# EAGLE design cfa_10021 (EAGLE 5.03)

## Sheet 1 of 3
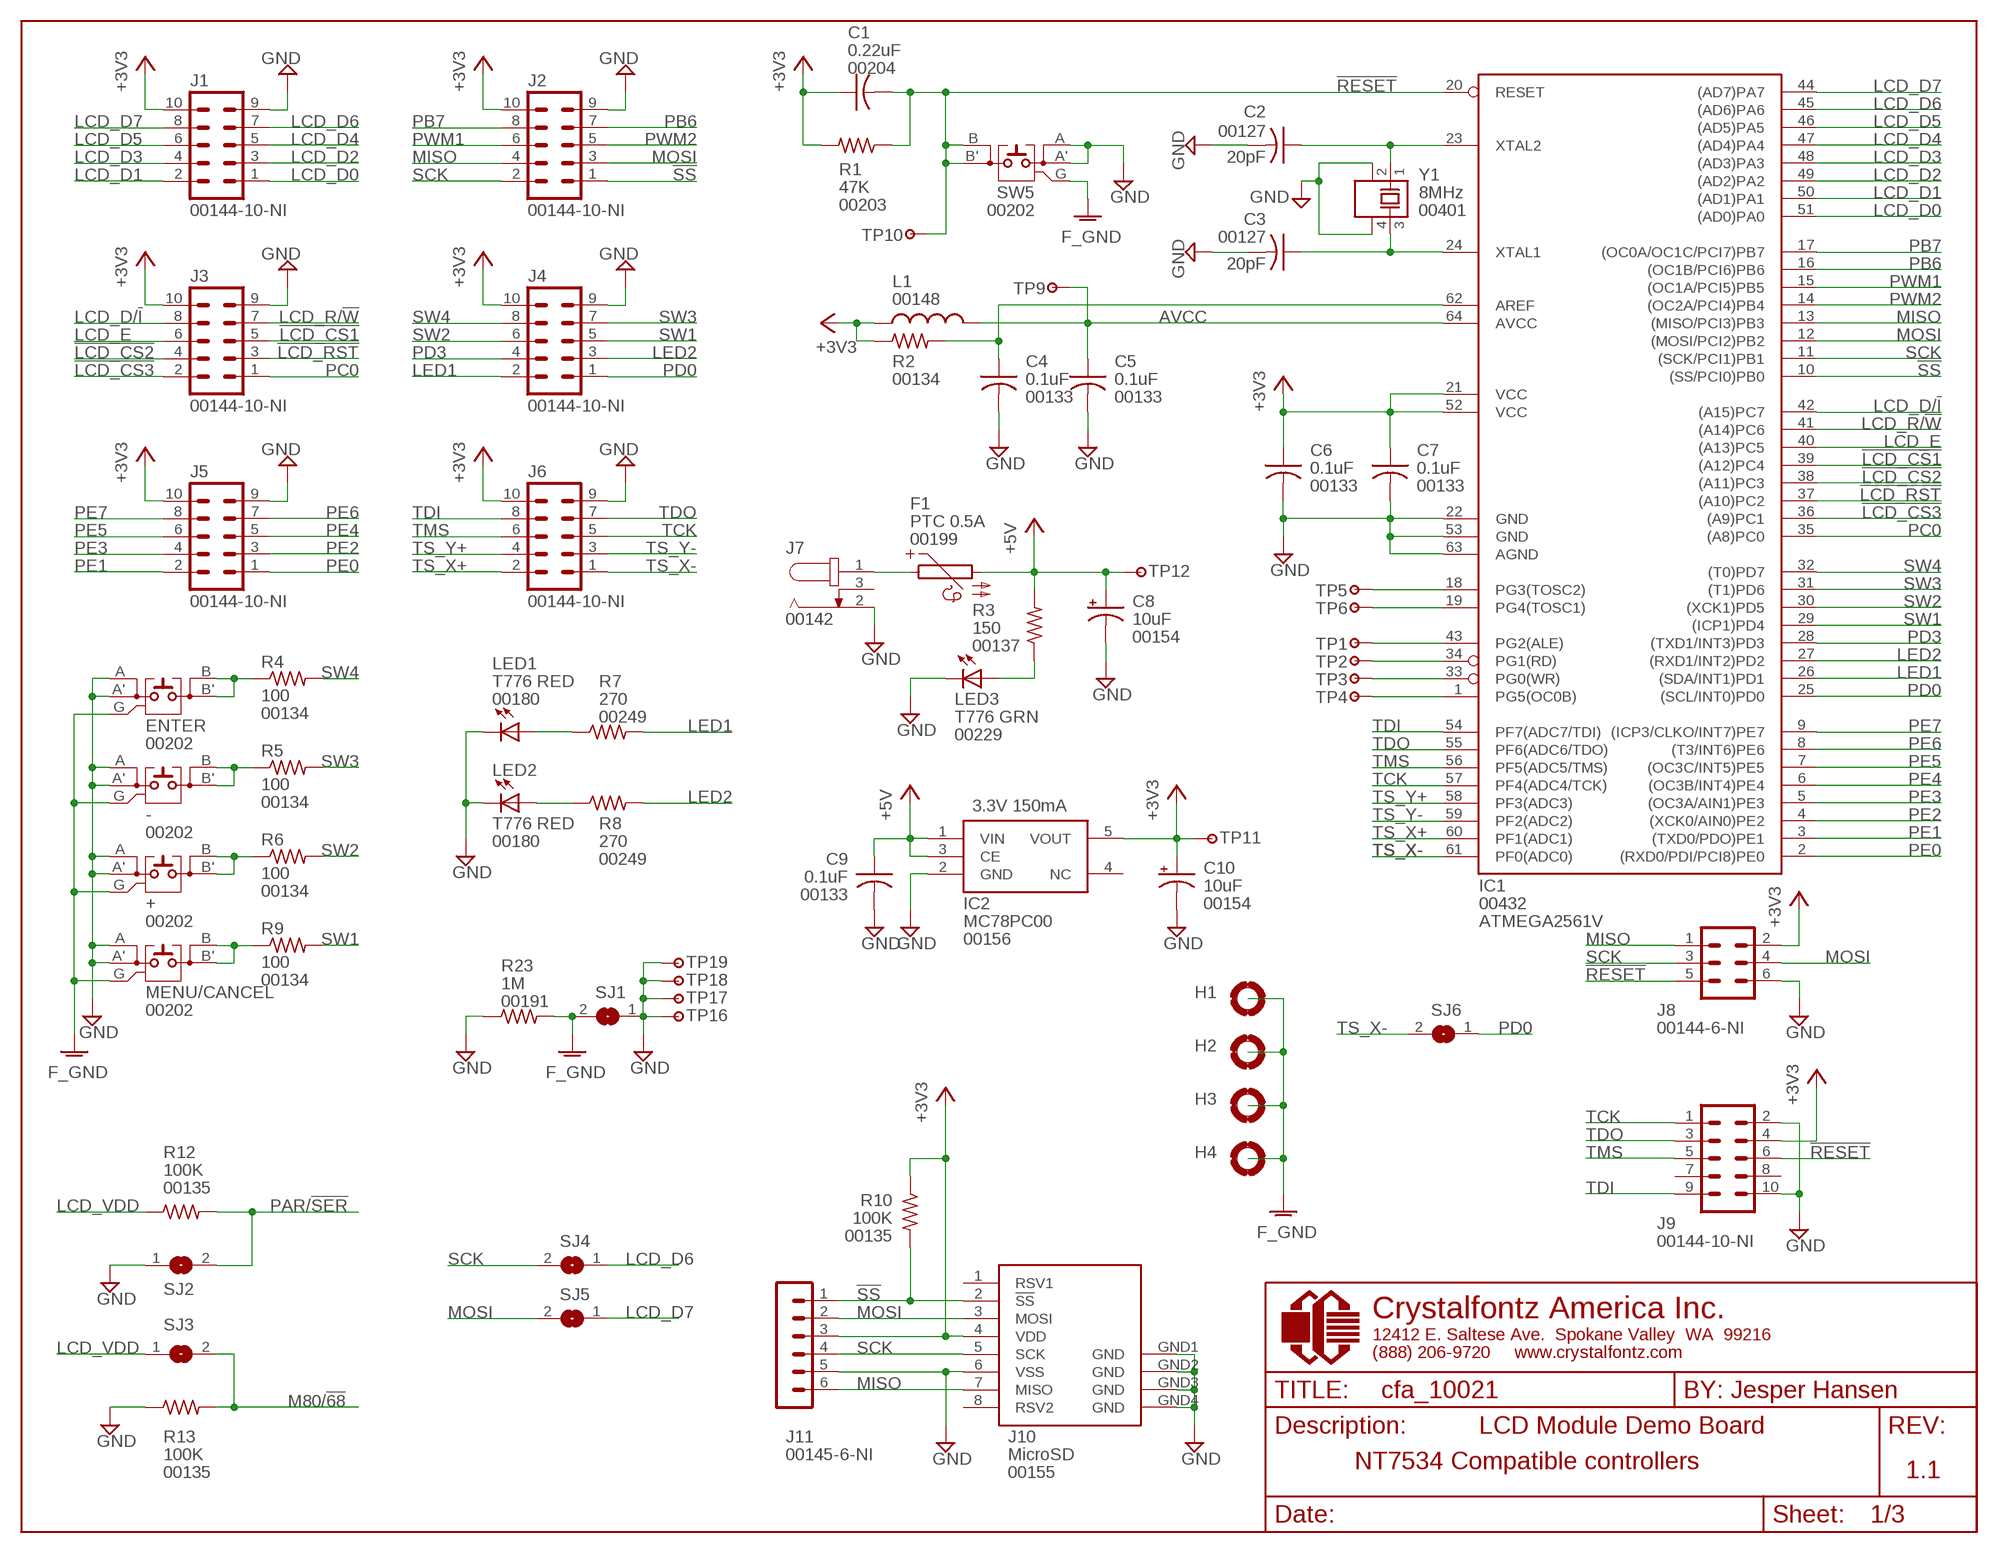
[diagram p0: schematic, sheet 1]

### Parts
+  00202  [EVQPB]
-  00202  [EVQPB]
C1  00204  [CAPC1608X90N]
C2  00127  [CAPC1608X87N]
C3  00127  [CAPC1608X87N]
C4  00133  [CAPC1608X87N]
C5  00133  [CAPC1608X87N]
C6  00133  [CAPC1608X87N]
C7  00133  [CAPC1608X87N]
C8  00154  [CAPMP6032X250N]
C9  00133  [CAPC1608X87N]
C10  00154  [CAPMP6032X250N]
ENTER  00202  [EVQPB]
F1  00199  [RESC3216X85N]
H1  MOUNT-PAD-ROUND3.2  [3,2-PAD]
H2  MOUNT-PAD-ROUND3.2  [3,2-PAD]
H3  MOUNT-PAD-ROUND3.2  [3,2-PAD]
H4  MOUNT-PAD-ROUND3.2  [3,2-PAD]
IC1  00432  [TQFP64-AEB]
IC2  00156  [SOT23-5L]
J1  00144-10-NI  [MA05-2]
J2  00144-10-NI  [MA05-2]
J3  00144-10-NI  [MA05-2]
J4  00144-10-NI  [MA05-2]
J5  00144-10-NI  [MA05-2]
J6  00144-10-NI  [MA05-2]
J7  00142  [PJ-102AH]
J8  00144-6-NI  [MA03-2]
J9  00144-10-NI  [MA05-2]
J10  00155  [3M_MICROSD]
J11  00145-6-NI  [MA06-1]
L1  00148  [R0805]
LED1  00180  [T776_LED_BOTTOM]
LED2  00180  [T776_LED_BOTTOM]
LED3  00229  [T776_LED_BOTTOM]
MENU/CANCEL  00202  [EVQPB]
R1  00203  [RESC1608X50N]
R2  00134  [RESC1608X38N]
R3  00137  [R0603]
R4  00134  [RESC1608X38N]
R5  00134  [RESC1608X38N]
R6  00134  [RESC1608X38N]
R7  00249  00137  [R0603]
R8  00249  00137  [R0603]
R9  00134  [RESC1608X38N]
R10  00135  [RESC1608X38N]
R12  00135  [RESC1608X38N]
R13  00135  [RESC1608X38N]
R23  00191  [RESC1608X55N]
SJ1  SJ  [SJ]
SJ2  SJ  [SJ]
SJ3  SJ  [SJ]
SJ4  SJ  [SJ]
SJ5  SJ  [SJ]
SJ6  SJ  [SJ]
SW5  00202  [EVQPB]
TP1  TP-VIA-3.2MM  [VIA-3.2MM-HOLE]
TP2  TP-VIA-3.2MM  [VIA-3.2MM-HOLE]
TP3  TP-VIA-3.2MM  [VIA-3.2MM-HOLE]
TP4  TP-VIA-3.2MM  [VIA-3.2MM-HOLE]
TP5  TP-VIA-3.2MM  [VIA-3.2MM-HOLE]
TP6  TP-VIA-3.2MM  [VIA-3.2MM-HOLE]
TP9  TP-VIA-1.0MM  [VIA-1MM-HOLE]
TP10  TP-VIA-1.0MM  [VIA-1MM-HOLE]
TP11  TP-VIA-1.0MM  [VIA-1MM-HOLE]
TP12  TP-VIA-1.0MM  [VIA-1MM-HOLE]
TP16  TP-VIA-1.0MM  [VIA-1MM-HOLE]
TP17  TP-VIA-1.0MM  [VIA-1MM-HOLE]
TP18  TP-VIA-1.0MM  [VIA-1MM-HOLE]
TP19  TP-VIA-1.0MM  [VIA-1MM-HOLE]
Y1  00401  [ABM3B]

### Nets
!LCD_CS1: IC1.39((A12)PC4) J3.5 ; also sheet 2
!LCD_CS2: IC1.38((A11)PC3) J3.4
!LCD_CS3: IC1.36((A9)PC1) J3.2
!LCD_RST: IC1.37((A10)PC2) J3.3 ; also sheet 2
!RESET: C1.2 IC1.20(RESET) J8.5 J9.6 R1.1 SW5.B SW5.B' TP10.1
!SS: IC1.10((SS/PCI0)PB0) J2.1 J10.2(!SS) J11.1 R10.2
+3V3: C1.1 C6.1 C7.1 C10.1(+) IC1.21(VCC) IC1.52(VCC) IC2.5(VOUT) J1.10 J2.10 J3.10 J4.10 J5.10 J6.10 J8.2 J9.4 J10.4(VDD) J11.3 L1.1 R1.2 R2.1 R10.1 TP11.1 ; also sheet 2
+5V: C8.1(+) C9.1 F1.2 IC2.1(VIN) IC2.3(CE) R3.2 TP12.1 ; also sheet 2
AVCC: C5.1 IC1.64(AVCC) L1.2 TP9.1
FOO: +.A +.A' -.A -.A' C2.2 C3.2 C4.2 C5.2 C6.2 C7.2 C8.2(-) C9.2 C10.2(-) ENTER.A ENTER.A' IC1.22(GND) IC1.53(GND) IC1.63(AGND) IC2.2(GND) J1.9 J2.9 J3.9 J4.9 J5.9 J6.9 J7.2 J8.6 J9.2 J9.10 J10.6(VSS) J10.GND1(GND) J10.GND2(GND) J10.GND3(GND) J10.GND4(GND) J11.5 LED1.K(C) LED2.K(C) LED3.K(C) MENU/CANCEL.A MENU/CANCEL.A' R13.1 R23.1 SJ1.1 SJ2.1 SW5.A SW5.A' TP16.1 TP17.1 TP18.1 TP19.1 Y1.2(GND) Y1.4(GND) ; supply symbol labelled GND ; also sheet 2
GNDA: +.G -.G ENTER.G H1.B3,2(MOUNT) H2.B3,2(MOUNT) H3.B3,2(MOUNT) H4.B3,2(MOUNT) MENU/CANCEL.G R23.2 SJ1.2 SW5.G ; supply symbol labelled F_GND
LCD_D0: IC1.51((AD0)PA0) J1.1 ; also sheet 2
LCD_D1: IC1.50((AD1)PA1) J1.2 ; also sheet 2
LCD_D2: IC1.49((AD2)PA2) J1.3 ; also sheet 2
LCD_D3: IC1.48((AD3)PA3) J1.4 ; also sheet 2
LCD_D4: IC1.47((AD4)PA4) J1.5 ; also sheet 2
LCD_D5: IC1.46((AD5)PA5) J1.6 ; also sheet 2
LCD_D6: IC1.45((AD6)PA6) J1.7 SJ4.1 ; also sheet 2
LCD_D7: IC1.44((AD7)PA7) J1.8 SJ5.1 ; also sheet 2
LCD_D/!I: IC1.42((A15)PC7) J3.8 ; also sheet 2
LCD_E: IC1.40((A13)PC5) J3.6 ; also sheet 2
LCD_R/!W: IC1.41((A14)PC6) J3.7 ; also sheet 2
LCD_VDD: R12.1 SJ3.1 ; also sheet 2
LED1: IC1.26((SDA/INT1)PD1) J4.2 R7.2
LED2: IC1.27((RXD1/INT2)PD2) J4.3 R8.2
M80/!68: R13.2 SJ3.2 ; also sheet 2
MISO: IC1.13((MISO/PCI3)PB3) J2.4 J8.1 J10.7(MISO) J11.6
MOSI: IC1.12((MOSI/PCI2)PB2) J2.3 J8.4 J10.3(MOSI) J11.2 SJ5.2
N$1: C2.1 IC1.23(XTAL2) Y1.1
N$2: ENTER.B ENTER.B' R4.1
N$3: C3.1 IC1.24(XTAL1) Y1.3
N$4: -.B -.B' R5.1
N$5: IC1.19(PG4(TOSC1)) TP6.1
N$6: +.B +.B' R6.1
N$7: LED1.A R7.1
N$8: MENU/CANCEL.B MENU/CANCEL.B' R9.1
N$9: C4.1 IC1.62(AREF) R2.2
N$10: LED2.A R8.1
N$11: IC1.43(PG2(ALE)) TP1.1
N$13: IC1.34(PG1(RD)) TP2.1
N$14: F1.1 J7.1
N$15: IC1.33(PG0(WR)) TP3.1
N$17: LED3.A R3.1
N$18: IC1.18(PG3(TOSC2)) TP5.1
N$19: IC1.1(PG5(OC0B)) TP4.1
PAR/!SER: R12.2 SJ2.2 ; also sheet 2
PB6: IC1.16((OC1B/PCI6)PB6) J2.7
PB7: IC1.17((OC0A/OC1C/PCI7)PB7) J2.8
PC0: IC1.35((A8)PC0) J3.1
PD0: IC1.25((SCL/INT0)PD0) J4.1 SJ6.1
PD3: IC1.28((TXD1/INT3)PD3) J4.4
PE0: IC1.2((RXD0/PDI/PCI8)PE0) J5.1
PE1: IC1.3((TXD0/PDO)PE1) J5.2
PE2: IC1.4((XCK0/AIN0)PE2) J5.3
PE3: IC1.5((OC3A/AIN1)PE3) J5.4
PE4: IC1.6((OC3B/INT4)PE4) J5.5
PE5: IC1.7((OC3C/INT5)PE5) J5.6
PE6: IC1.8((T3/INT6)PE6) J5.7
PE7: IC1.9((ICP3/CLKO/INT7)PE7) J5.8
PWM1: IC1.15((OC1A/PCI5)PB5) J2.6 ; also sheet 2
PWM2: IC1.14((OC2A/PCI4)PB4) J2.5 ; also sheet 2
SCK: IC1.11((SCK/PCI1)PB1) J2.2 J8.3 J10.5(SCK) J11.4 SJ4.2
SW1: IC1.29((ICP1)PD4) J4.5 R9.2
SW2: IC1.30((XCK1)PD5) J4.6 R6.2
SW3: IC1.31((T1)PD6) J4.7 R5.2
SW4: IC1.32((T0)PD7) J4.8 R4.2
TCK: IC1.57(PF4(ADC4/TCK)) J6.5 J9.1
TDI: IC1.54(PF7(ADC7/TDI)) J6.8 J9.9
TDO: IC1.55(PF6(ADC6/TDO)) J6.7 J9.3
TMS: IC1.56(PF5(ADC5/TMS)) J6.6 J9.5
TS_X+: IC1.60(PF1(ADC1)) J6.2 ; also sheet 2
TS_X-: IC1.61(PF0(ADC0)) J6.1 SJ6.2 ; also sheet 2
TS_Y+: IC1.58(PF3(ADC3)) J6.4 ; also sheet 2
TS_Y-: IC1.59(PF2(ADC2)) J6.3 ; also sheet 2
Unconnected: IC2.4(NC) J7.3 J9.7 J9.8 J10.1(RSV1) J10.8(RSV2)

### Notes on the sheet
- 0.22uF
- 20pF
- 47K
- 8MHz
- 20pF
- 0.1uF | 0.1uF
- 0.1uF | 0.1uF
- PTC 0.5A
- 10uF
- 150
- T776 RED
- 100 | 270
- T776 GRN
- 100
- 3.3V 150mA
- T776 RED
- 270
- 100 | 0.1uF
- 10uF
- MC78PC00 | ATMEGA2561V
- 100
- 1M
- 100K
- 100K
- LCD Module Demo Board
- 100K | MicroSD
- NT7534 Compatible controllers
- 1.1

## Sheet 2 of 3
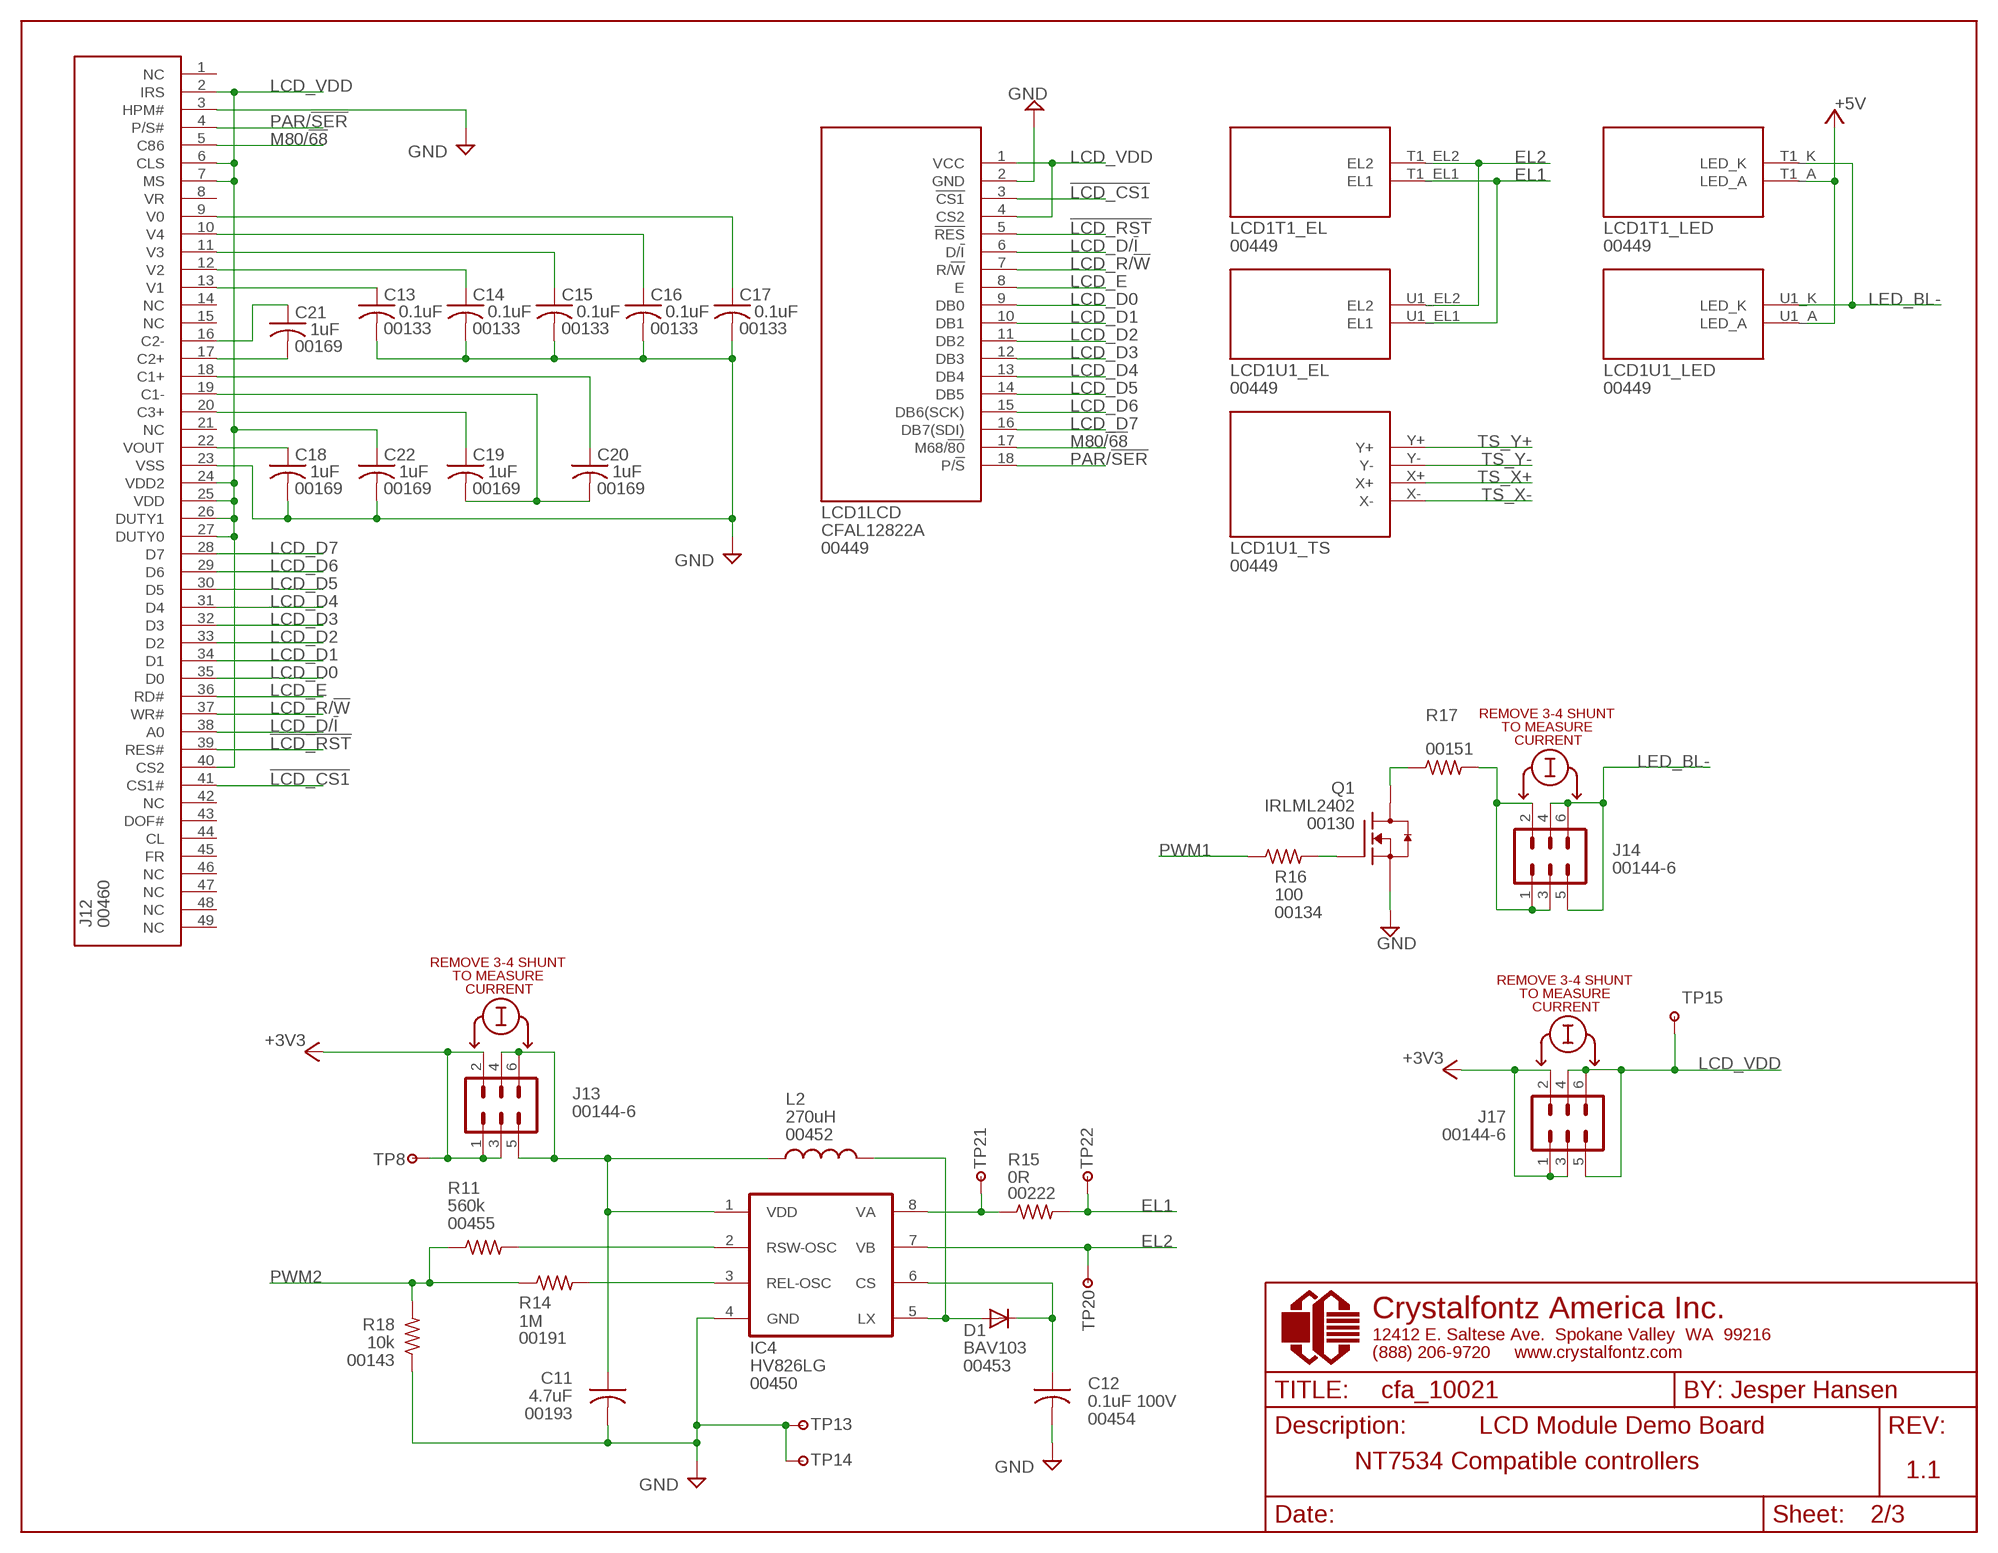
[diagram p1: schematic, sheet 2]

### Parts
C11  00193  [CAPC2012X51N]
C12  00454  [C0805]
C13  00133  [CAPC1608X87N]
C14  00133  [CAPC1608X87N]
C15  00133  [CAPC1608X87N]
C16  00133  [CAPC1608X87N]
C17  00133  [CAPC1608X87N]
C18  00169  [CAPC2012X125N]
C19  00169  [CAPC2012X125N]
C20  00169  [CAPC2012X125N]
C21  00169  [CAPC2012X125N]
C22  00169  [CAPC2012X125N]
D1  00453  [SOD80C]
IC4  00450  [SO08]
J12  00460  [CFAX12864_TAB]
J13  00144-6  [MA03-2]
J14  00144-6  [MA03-2]
J17  00144-6  [MA03-2]
L2  00452  [IND-1210]
LCD1  00449  [CFAX12864_ALL]
Q1  00130  [SOT23]
R11  00455  [RESC1608X55N]
R14  00191  [RESC1608X55N]
R15  00222  [RESC1608X38N]
R16  00134  [RESC1608X38N]
R17  00151  [R2010]
R18  00143  [RESC1608X38N]
TP8  TP-VIA-1.0MM  [VIA-1MM-HOLE]
TP13  TP-VIA-1.0MM  [VIA-1MM-HOLE]
TP14  TP-VIA-1.0MM  [VIA-1MM-HOLE]
TP15  TP-VIA-1.0MM  [VIA-1MM-HOLE]
TP20  TP-VIA-1.0MM  [VIA-1MM-HOLE]
TP21  TP-VIA-1.0MM  [VIA-1MM-HOLE]
TP22  TP-VIA-1.0MM  [VIA-1MM-HOLE]

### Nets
!LCD_CS1: J12.41(CS1#) LCD1.3(LCD:!CS1) ; also sheet 1
!LCD_RST: J12.39(RES#) LCD1.5(LCD:!RES) ; also sheet 1
+3V3: J13.1 J13.2 J13.3 J17.1 J17.2 J17.3 TP8.1 ; also sheet 1
+5V: LCD1.T1_A(T1_LED:LED_A) LCD1.U1_A(U1_LED:LED_A) ; also sheet 1
EL1: LCD1.T1_EL1(T1_EL:EL1) LCD1.U1_EL1(U1_EL:EL1) R15.2 TP22.1
EL2: IC4.7(VB) LCD1.T1_EL2(T1_EL:EL2) LCD1.U1_EL2(U1_EL:EL2) TP20.1
FOO: C11.2 C12.2 C13.2 C14.2 C15.2 C16.2 C17.2 C18.2 C22.2 IC4.4(GND) J12.3(HPM#) J12.23(VSS) LCD1.2(LCD:GND) Q1.2(S) R18.1 TP13.1 TP14.1 ; supply symbol labelled GND ; also sheet 1
LCD_D0: J12.35(D0) LCD1.9(LCD:DB0) ; also sheet 1
LCD_D1: J12.34(D1) LCD1.10(LCD:DB1) ; also sheet 1
LCD_D2: J12.33(D2) LCD1.11(LCD:DB2) ; also sheet 1
LCD_D3: J12.32(D3) LCD1.12(LCD:DB3) ; also sheet 1
LCD_D4: J12.31(D4) LCD1.13(LCD:DB4) ; also sheet 1
LCD_D5: J12.30(D5) LCD1.14(LCD:DB5) ; also sheet 1
LCD_D6: J12.29(D6) LCD1.15(LCD:DB6(SCK)) ; also sheet 1
LCD_D7: J12.28(D7) LCD1.16(LCD:DB7(SDI)) ; also sheet 1
LCD_D/!I: J12.38(A0) LCD1.6(LCD:D/!I) ; also sheet 1
LCD_E: J12.36(RD#) LCD1.8(LCD:E) ; also sheet 1
LCD_R/!W: J12.37(WR#) LCD1.7(LCD:R/!W) ; also sheet 1
LCD_VDD: C22.1 J12.2(IRS) J12.6(CLS) J12.7(MS) J12.24(VDD2) J12.25(VDD) J12.26(DUTY1) J12.27(DUTY0) J12.40(CS2) J17.4 J17.5 J17.6 LCD1.1(LCD:VCC) LCD1.4(LCD:CS2) TP15.1 ; also sheet 1
LED_BL-: J14.4 J14.5 J14.6 LCD1.T1_K(T1_LED:LED_K) LCD1.U1_K(U1_LED:LED_K)
M80/!68: J12.5(C86) LCD1.17(LCD:M68/!80) ; also sheet 1
N$12: C12.1 D1.C IC4.6(CS)
N$16: IC4.8(VA) R15.1 TP21.1
N$20: IC4.2(RSW-OSC) R11.2
N$21: IC4.3(REL-OSC) R14.2
N$22: C11.1 IC4.1(VDD) J13.4 J13.5 J13.6 L2.1
N$25: J14.1 J14.2 J14.3 R17.2
N$28: C18.1 J12.22(VOUT)
N$29: C19.2 C20.2 J12.19(C1-)
N$30: Q1.3(D) R17.1
N$31: Q1.1(G) R16.2
N$32: D1.A IC4.5(LX) L2.2
N$33: C19.1 J12.20(C3+)
N$34: C20.1 J12.18(C1+)
N$35: C21.2 J12.17(C2+)
N$36: C21.1 J12.16(C2-)
N$37: C13.1 J12.13(V1)
N$38: C14.1 J12.12(V2)
N$39: C15.1 J12.11(V3)
N$40: C16.1 J12.10(V4)
N$41: C17.1 J12.9(V0)
PAR/!SER: J12.4(P/S#) LCD1.18(LCD:P/!S) ; also sheet 1
PWM1: R16.1 ; also sheet 1
PWM2: R11.1 R14.1 R18.2 ; also sheet 1
TS_X+: LCD1.X+(U1_TS:X+) ; also sheet 1
TS_X-: LCD1.X-(U1_TS:X-) ; also sheet 1
TS_Y+: LCD1.Y+(U1_TS:Y+) ; also sheet 1
TS_Y-: LCD1.Y-(U1_TS:Y-) ; also sheet 1
Unconnected: J12.1(NC) J12.8(VR) J12.14(NC) J12.15(NC) J12.21(NC) J12.42(NC) J12.43(DOF#) J12.44(CL) J12.45(FR) J12.46(NC) J12.47(NC) J12.48(NC) J12.49(NC)

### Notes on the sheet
- 0.1uF | 0.1uF | 0.1uF | 0.1uF | 0.1uF
- 1uF
- 1uF | 1uF | 1uF | 1uF
- CFAL12822A
- REMOVE 3-4 SHUNT
- TO MEASURE
- CURRENT
- IRLML2402
- 100
- REMOVE 3-4 SHUNT
- TO MEASURE
- REMOVE 3-4 SHUNT
- CURRENT
- TO MEASURE
- CURRENT
- 270uH
- 0R
- 560k
- 1M
- 10k
- BAV103
- HV826LG
- 4.7uF
- 0.1uF 100V
- LCD Module Demo Board
- NT7534 Compatible controllers
- 1.1

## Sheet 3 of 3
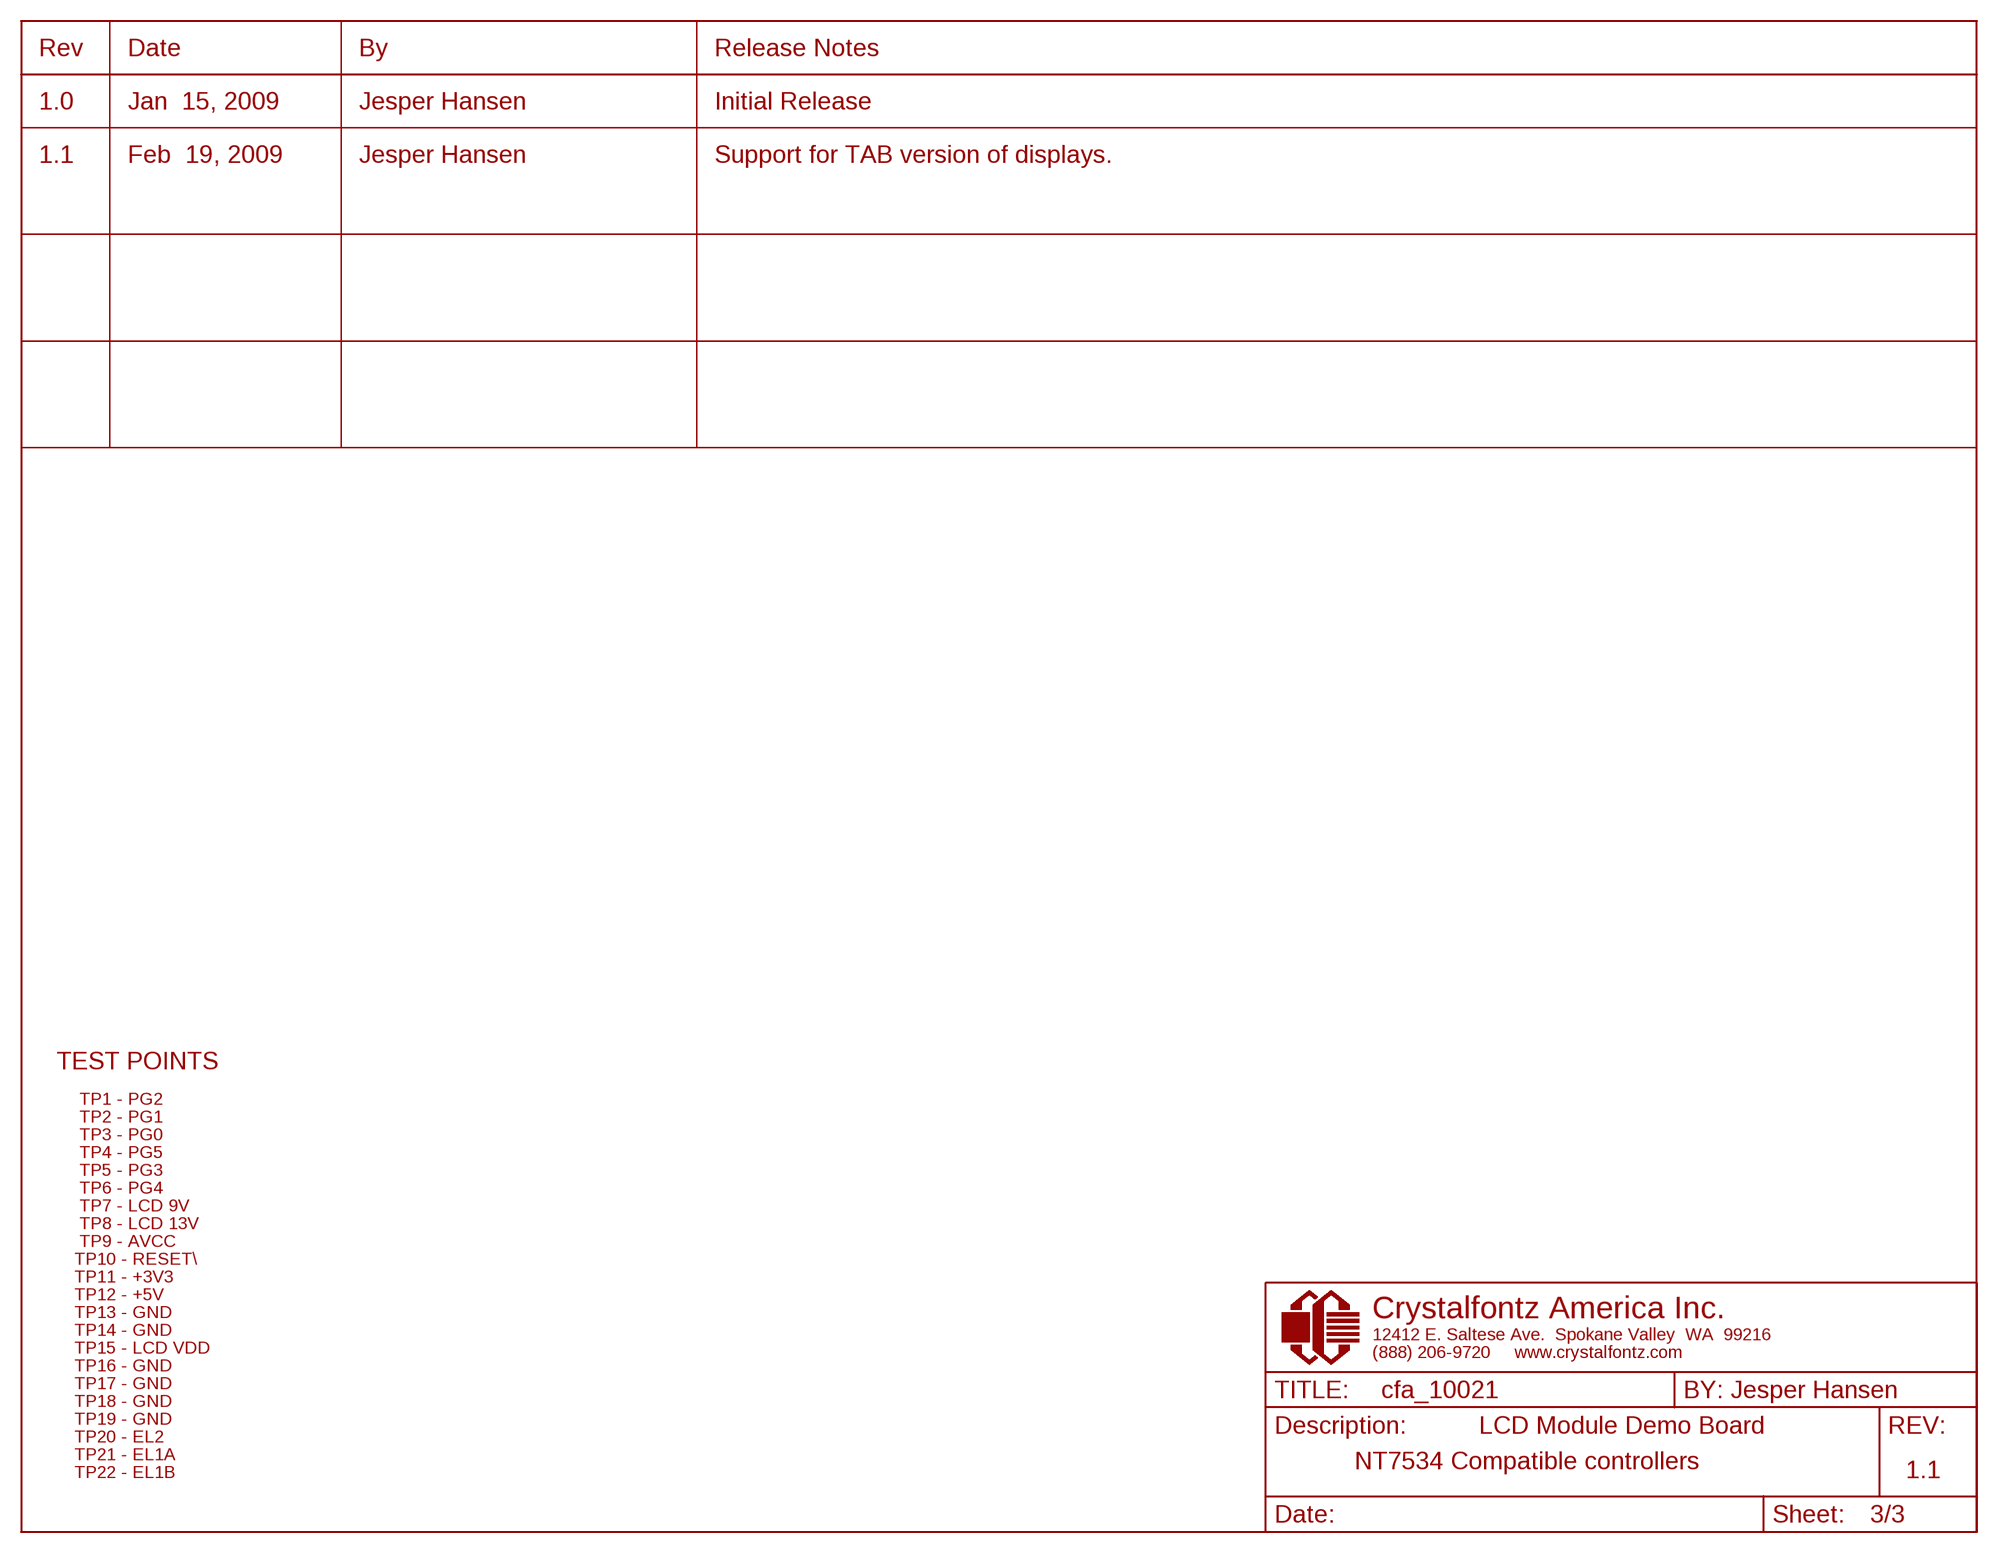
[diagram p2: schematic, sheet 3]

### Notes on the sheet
- Rev | Date | By | Release Notes
- 1.0 | Jan  15, 2009 | Jesper Hansen | Initial Release
- 1.1 | Feb  19, 2009 | Jesper Hansen | Support for TAB version of displays.
- TEST POINTS
- TP1 - PG2
- TP2 - PG1
- TP3 - PG0
- TP4 - PG5
- TP5 - PG3
- TP6 - PG4
- TP7 - LCD 9V
- TP8 - LCD 13V
- TP9 - AVCC
- TP10 - RESET\\
- TP11 - +3V3
- TP12 - +5V
- TP13 - GND
- TP14 - GND
- TP15 - LCD VDD
- TP16 - GND
- TP17 - GND
- TP18 - GND
- TP19 - GND
- LCD Module Demo Board
- TP20 - EL2
- TP21 - EL1A
- NT7534 Compatible controllers
- TP22 - EL1B | 1.1

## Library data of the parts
+ - ENTER MENU/CANCEL SW5 = proddev_lib:00202: SPST MOM W/GND, 6MM LIGHT TOUCH SW W/GND H=7 TH
C1 = proddev_lib:00204: 0.22uF 10V, CAP .22UF 10V CERAMIC X5R 0603
C2 C3 = proddev_lib:00127: 20pF, CAP CER 20PF 50V 5% C0G 0603
C4-C7 C9 C13-C17 = proddev_lib:00133: 0.1uF 16V, CAP .1UF 16V CERAMIC X7R 0603
C8 C10 = proddev_lib:00154: 10uF 10V, CAP TANT 10UF 10V 10% LOESR SMD
C11 = proddev_lib:00193: 4.7UF 10V, CAP CER 4.7UF 10V X7R 0805
C12 = proddev_lib2:00454: CAP CER .10UF 100V X7R 10% 0805
C18-C22 = proddev_lib:00169: 1.0UF 35V, CAP CER 1.0UF 35V X7R 0805
D1 = proddev_lib2:00453: DIODE SW 200V 250MA SOD80C
F1 = proddev_lib:00199: 500mA, PTC RESETTABLE .50A 13.2V 1206
H1-H4 = holes:MOUNT-PAD-ROUND: MOUNTING PAD, round
IC1 = proddev_lib2:00432: ATmega2561V-8AU, IC AVR MCU 256K 8MHZ LOW-VOLTAGE 64TQFP 256 Kbytes FLASH 8 Kbytes SRAM 4 Kbytes EEPROM DUAL USART 8-channel 10 bit ADC
IC2 = proddev_lib:00156: MC78PC33, IC REG LDO 150MA 3.3V LN SOT23-5
IC4 = proddev_lib2:00450: HV826 High Voltage EL Lamp Driver Features 1.8 to 3.5V operating supply voltage DC to AC conversion Output voltage regulation Adjustable output lamp frequency Adjustable converter frequency Enable/disable function Applications Pagers Portable Transceiver Cellular phones Remote control units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
J1-J6 J9 = proddev_lib:00144-10-NI: 2X5 HDR, CONN HDR BRKWAY .100 VERT
J7 = proddev_lib:00142: 2.1x5.5MM, CONN PWR JACK 2.1X5.5MM HIGH CUR
J8 = proddev_lib:00144-6-NI: 2X3 HDR, CONN HDR BRKWAY .100 VERT
J10 = proddev_lib:00155: MICROSD SOCKET, CONN EJECT MICROSD PUSH-PUSH SMD
J11 = proddev_lib:00145-6-NI: 1X6 HDR, CONN HDR BRKWAY .100 VERT
J12 = proddev_lib2:00460: TAB connector for CFAX displays
J13 J14 J17 = proddev_lib:00144-6: 2X3 HDR, CONN HDR BRKWAY .100 VERT
L1 = proddev_lib:00148: 10uH, FERRITE CHIP 1000 OHM 200MA 0805
L2 = proddev_lib2:00452: INDUCTOR 270UH 5% 40MA 1210
LCD1 = proddev_lib2:00449: Multidesign for all CFAX12864 variants
LED1 LED2 = proddev_lib:00180: LST776, LED SUP RED REV GULWNG 645NM SMD
LED3 = proddev_lib:00229: LED GRN, LED PURE GRN REV GLWNG 562NM SMD
Q1 = proddev_lib:00130: IRLML2402, MOSFET N-CH 20V 1.2A SOT-23
R1 = proddev_lib:00203: 47K 1/10W 5%, RES 47K OHM 1/10W 5% 0603 SMD
R2 R4-R6 R9 R16 = proddev_lib:00134: 100, RES 100 OHM 1/10W 5% 0603 SMD
R3 R7 R8 = proddev_lib:00137: 150, RES 150 OHM 1/10W 5% 0603 SMD
R10 R12 R13 = proddev_lib:00135: 100K, RES 100K OHM 1/10W 5% 0603 SMD
R11 = proddev_lib2:00455: RES 560K OHM 1/10W 1% 0603 SMD
R14 R23 = proddev_lib:00191: 1.0M 1/10W 1%, RES 1.00M OHM 1/10W 1% 0603 SMD
R15 = proddev_lib:00222: 0.0 OHM, RES 0.0 OHM 1/10W 5% 0603 SMD
R17 = proddev_lib:00151: R 1/2W 2010, BACKLIGHT RES 1/2W 2010 SMD
R18 = proddev_lib:00143: 10K, RES 10K OHM 1/10W 5% 0603 SMD
SJ1-SJ6 = proddev_lib:SJ: SMD solder JUMPER
TP1-TP6 = proddev_lib:TP-VIA-3.2MM: 3.2MM Hole Via TP
TP8-TP22 = proddev_lib:TP-VIA-1.0MM: TP 1MM HOLE
Y1 = proddev_lib2:00401: Crystal; ABM3B Ceramic SMD Crystal, 5x3.2mm

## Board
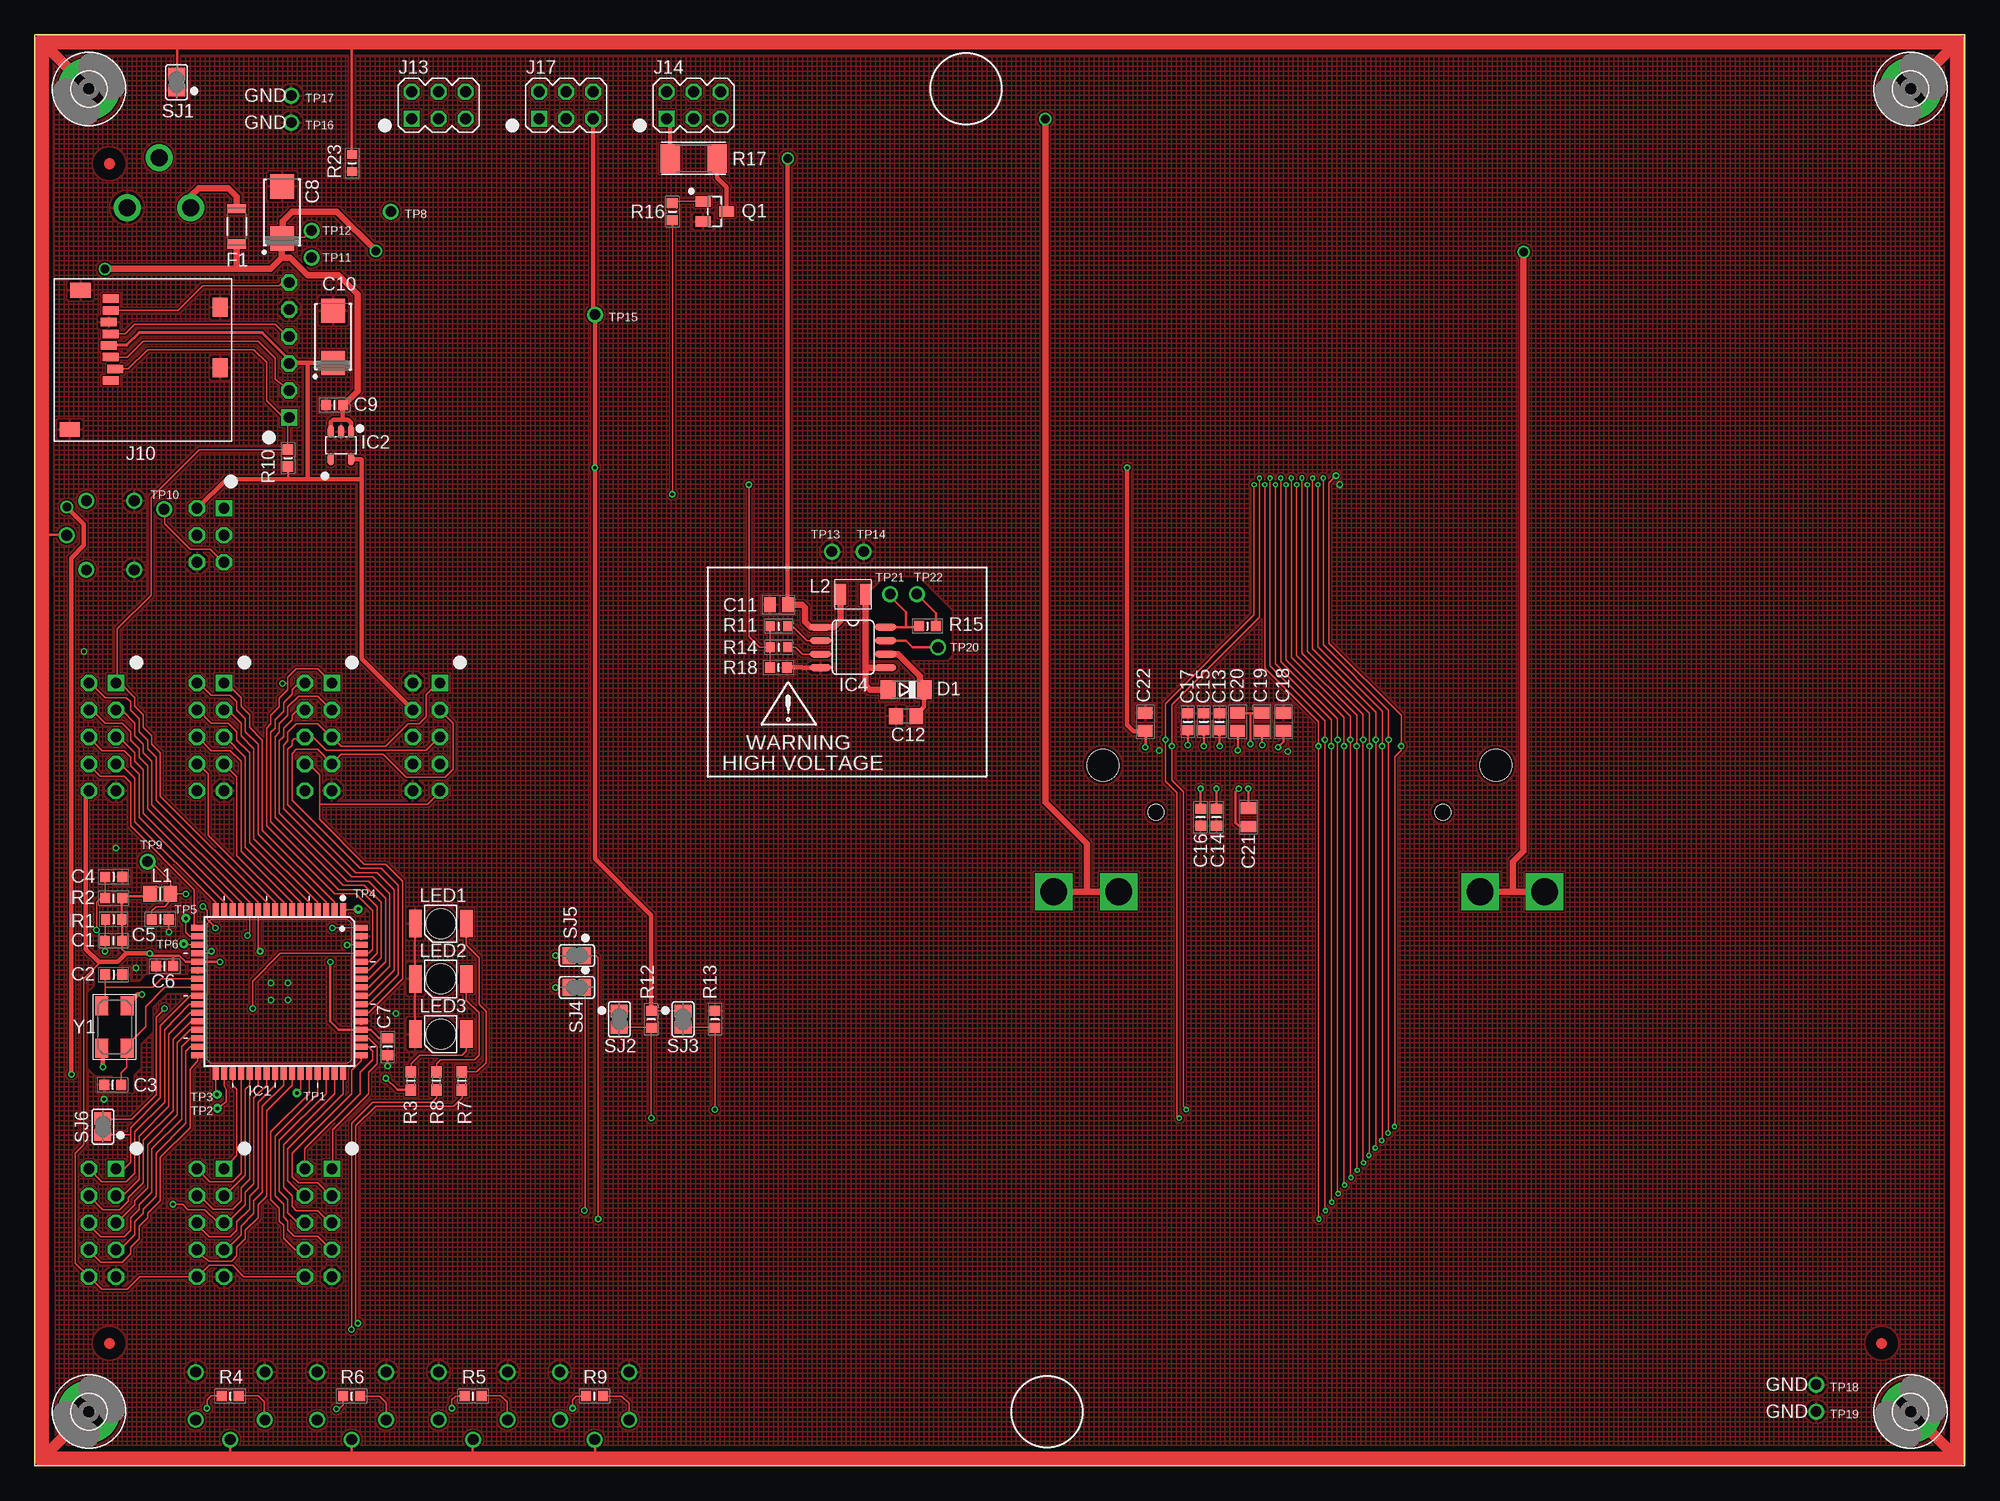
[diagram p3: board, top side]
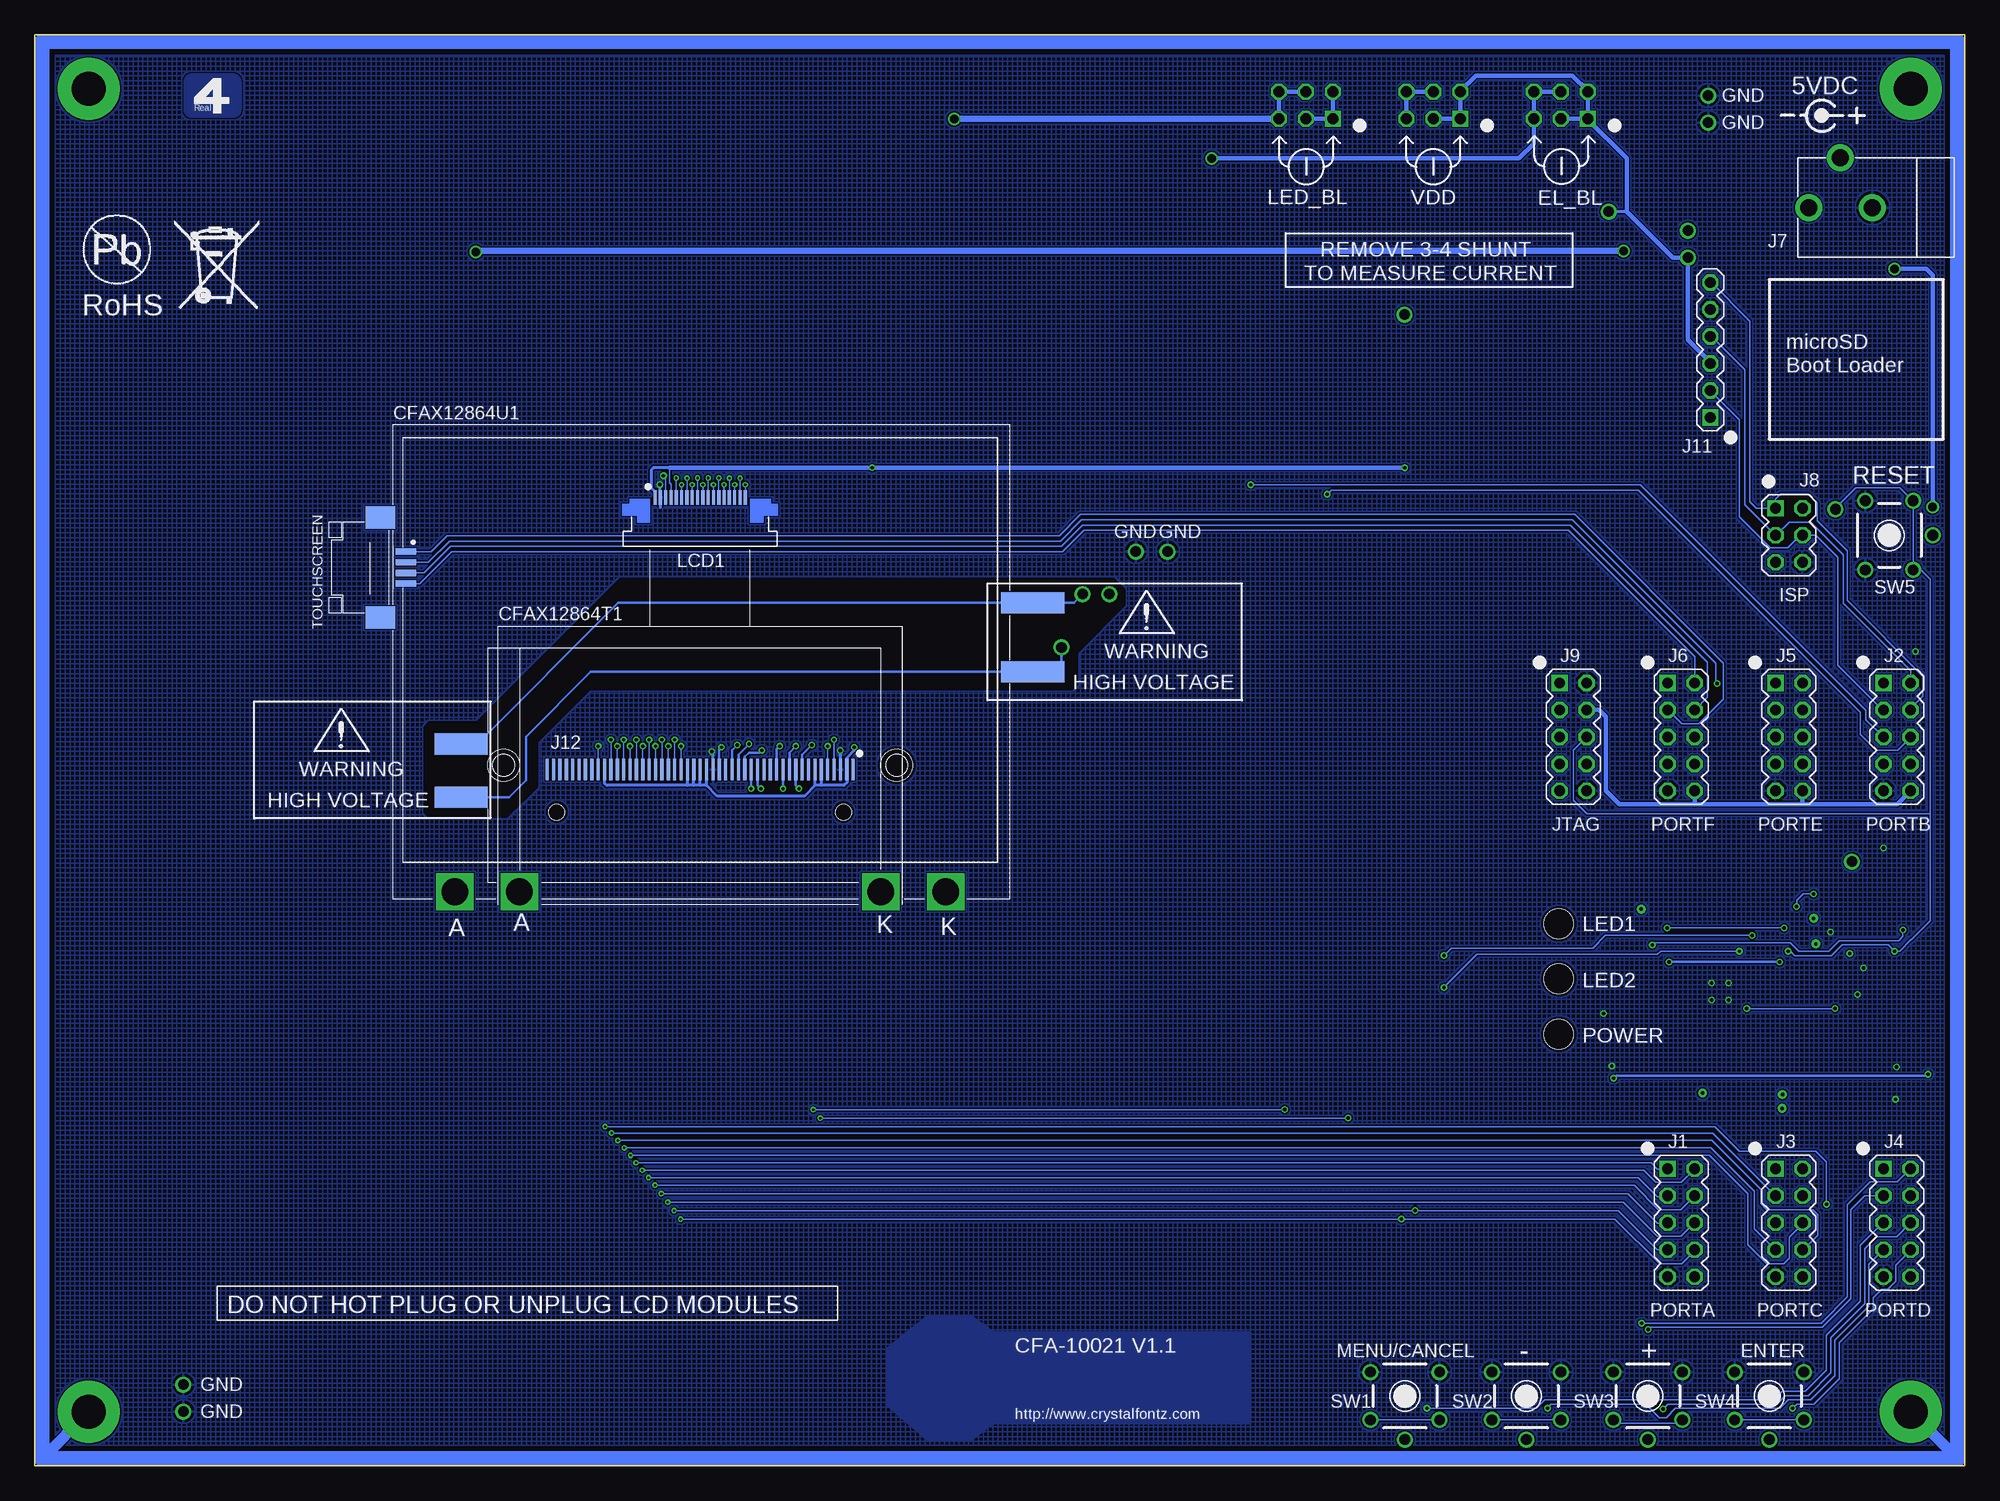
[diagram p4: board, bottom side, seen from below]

Size 181.61 x 134.62 mm. Coordinates in mm from the lower left corner, seen from the top.
Outline: 0,0 181.57,0 181.57,134.62 0,134.62
Outline: 0,0 181.61,0 181.61,134.62 0,134.62
Outline: 0,134.62 0,0
Copper layers (1*2+15*16): Top 0.0254mm / dielectric 0.2032mm / Route2 0.0254mm / dielectric 1.4986mm / Route15 0.0254mm / dielectric 0.2032mm / Bottom 0.0254mm
Design rules "cadint-2layer": minimum track width 5mil, minimum drill 0.31mm, track to track 5mil, track to pad 5mil, pad to pad 5mil, via to via 5mil, smd to smd 5mil, copper to edge 10mil, drill to drill 10mil, minimum pad ring 10mil, minimum via ring 6mil, stop-mask expansion 0mil, vias tented up to drill 0mil, thermal gap 10mil
tRestrict: area 5.5,10 to 8.5,13; area 5.5,121 to 8.5,124; area 172.3,10 to 175.3,13; area 5.1,35.2 to 16.2,46.7; area 78.4,75.9 to 86.2,83.5
bRestrict: area 79,61 to 145,83.5

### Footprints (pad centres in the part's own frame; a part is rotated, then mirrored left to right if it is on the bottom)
EVQPB = drill 1 round: A -2.25,3.25; A' -2.25,-3.25; B 2.25,3.25; B' 2.25,-3.25; G 4.1,0
CAPC1608X90N = smd 0.9 x 0.95: 1 -0.8,0; 2 0.8,0
CAPC1608X87N = smd 0.95 x 1: 1 -0.8,0; 2 0.8,0
CAPMP6032X250N = smd 2.3 x 2.25: 1 -2.45,0; 2 2.45,0
CAPC2012X51N = smd 1.1 x 1.4: 1 -0.85,0; 2 0.85,0
C0805 = smd 1.3 x 1.5: 1 -0.95,0; 2 0.95,0
CAPC2012X125N = smd 1.1 x 1.4: 1 -0.85,0; 2 0.85,0
SOD80C = smd 1.4 x 1.8: A 1.7,0; C -1.7,0
RESC3216X85N = smd 0.85 x 1.8: 1 -1.65,0; 2 1.65,0
3,2-PAD = drill 3.2 pad 5.842 round: B3,2 0,0
TQFP64-AEB = smd 1.194 x 0.559: 1 -7.7,6; 2 -7.7,5.2; 3 -7.7,4.4; 4 -7.7,3.6; 5 -7.7,2.8; 6 -7.7,2; 7 -7.7,1.2; 8 -7.7,0.4; 9 -7.7,-0.4; 10 -7.7,-1.2; 11 -7.7,-2; 12 -7.7,-2.8; 13 -7.7,-3.6; 14 -7.7,-4.4; 15 -7.7,-5.2; 16 -7.7,-6; 33 7.7,-6; 34 7.7,-5.2; 35 7.7,-4.4; 36 7.7,-3.6; 37 7.7,-2.8; 38 7.7,-2; 39 7.7,-1.2; 40 7.7,-0.4; 41 7.7,0.4; 42 7.7,1.2; 43 7.7,2; 44 7.7,2.8; 45 7.7,3.6; 46 7.7,4.4; 47 7.7,5.2; 48 7.7,6 | smd 0.559 x 1.194: 17 -6,-7.7; 18 -5.2,-7.7; 19 -4.4,-7.7; 20 -3.6,-7.7; 21 -2.8,-7.7; 22 -2,-7.7; 23 -1.2,-7.7; 24 -0.4,-7.7; 25 0.4,-7.7; 26 1.2,-7.7; 27 2,-7.7; 28 2.8,-7.7; 29 3.6,-7.7; 30 4.4,-7.7; 31 5.2,-7.7; 32 6,-7.7; 49 6,7.7; 50 5.2,7.7; 51 4.4,7.7; 52 3.6,7.7; 53 2.8,7.7; 54 2,7.7; 55 1.2,7.7; 56 0.4,7.7; 57 -0.4,7.7; 58 -1.2,7.7; 59 -2,7.7; 60 -2.8,7.7; 61 -3.6,7.7; 62 -4.4,7.7; 63 -5.2,7.7; 64 -6,7.7
SOT23-5L = smd 0.55 x 1.2: 1 -0.95,-1.3; 2 0,-1.3; 3 0.95,-1.3; 4 0.95,1.3; 5 -0.95,1.3
SO08 = smd 0.66 x 2.032: 1 -1.905,-3.073; 2 -0.635,-3.073; 3 0.635,-3.073; 4 1.905,-3.073; 5 1.905,3.073; 6 0.635,3.073; 7 -0.635,3.073; 8 -1.905,3.073
MA05-2 = drill 1.016 square: 1 -5.08,-1.27 | drill 1.016 octagon: 2 -5.08,1.27; 3 -2.54,-1.27; 4 -2.54,1.27; 5 0,-1.27; 6 0,1.27; 7 2.54,-1.27; 8 2.54,1.27; 9 5.08,-1.27; 10 5.08,1.27
PJ-102AH = drill 1.6 pad 2.54 round: 1 -3,0; 2 3,0; 3 0,4.7
MA03-2 = drill 1.016 square: 1 -2.54,-1.27 | drill 1.016 octagon: 2 -2.54,1.27; 3 0,-1.27; 4 0,1.27; 5 2.54,-1.27; 6 2.54,1.27
3M_MICROSD = smd 0.8 x 1.5: 1 -6.89,10.3; 2 -5.79,9.9; 3 -4.69,10.3; 4 -3.59,10.5; 5 -2.49,10.3; 6 -1.39,10.5; 7 -0.29,10.3; 8 0.81,10.3 | smd 1.8 x 1.4: GND1 0,0; GND2 -5.7,0 | smd 1.4 x 1.9: GND3 -11.5,14.15; GND4 1.6,13.15
MA06-1 = drill 1.016 square: 1 -6.35,0 | drill 1.016 octagon: 2 -3.81,0; 3 -1.27,0; 4 1.27,0; 5 3.81,0; 6 6.35,0
CFAX12864_TAB = smd 0.3 x 2: 1 14.4,-25.5; 2 13.8,-25.5; 3 13.2,-25.5; 4 12.6,-25.5; 5 12,-25.5; 6 11.4,-25.5; 7 10.8,-25.5; 8 10.2,-25.5; 9 9.6,-25.5; 10 9,-25.5; 11 8.4,-25.5; 12 7.8,-25.5; 13 7.2,-25.5; 14 6.6,-25.5; 15 6,-25.5; 16 5.4,-25.5; 17 4.8,-25.5; 18 4.2,-25.5; 19 3.6,-25.5; 20 3,-25.5; 21 2.4,-25.5; 22 1.8,-25.5; 23 1.2,-25.5; 24 0.6,-25.5; 25 0,-25.5; 26 -0.6,-25.5; 27 -1.2,-25.5; 28 -1.8,-25.5; 29 -2.4,-25.5; 30 -3,-25.5; 31 -3.6,-25.5; 32 -4.2,-25.5; 33 -4.8,-25.5; 34 -5.4,-25.5; 35 -6,-25.5; 36 -6.6,-25.5; 37 -7.2,-25.5; 38 -7.8,-25.5; 39 -8.4,-25.5; 40 -9,-25.5; 41 -9.6,-25.5; 42 -10.2,-25.5; 43 -10.8,-25.5; 44 -11.4,-25.5; 45 -12,-25.5; 46 -12.6,-25.5; 47 -13.2,-25.5; 48 -13.8,-25.5; 49 -14.4,-25.5 | hole 1.5: -13.5,-29.5; 13.5,-29.5
R0805 = smd 1.3 x 1.5: 1 -0.95,0; 2 0.95,0
IND-1210 = smd 1 x 2: 1 -1.15,0; 2 1.15,0
CFAX12864_ALL = smd 0.3 x 1.4: 1 -4.25,0.1; 2 -3.75,0.1; 3 -3.25,0.1; 4 -2.75,0.1; 5 -2.25,0.1; 6 -1.75,0.1; 7 -1.25,0.1; 8 -0.75,0.1; 9 -0.25,0.1; 10 0.25,0.1; 11 0.75,0.1; 12 1.25,0.1; 13 1.75,0.1; 14 2.25,0.1; 15 2.75,0.1; 16 3.25,0.1; 17 3.75,0.1; 18 4.25,0.1 | smd 2.8 x 2.1: P$1 -30.1,-1.8; P$2 -30.1,-11.2 | drill 2.5 square: T1_A -17,-37; T1_K 17,-37; U1_A -23.1,-37; U1_K 23.1,-37 | smd 5 x 2: T1_EL1 -22.5,-23.1; T1_EL2 -22.5,-28.1 | smd 6 x 2: U1_EL1 31.31,-9.81; U1_EL2 31.31,-16.31 | smd 1.9 x 0.6: X+ -27.7,-8; X- -27.7,-6; Y+ -27.7,-7; Y- -27.7,-5 | hole 3: -18.5,-25.1; 18.5,-25.1
T776_LED_BOTTOM = smd 1.2 x 2.6: A -2.4,0; K 2.4,0 | hole 2.8: 0,0
SOT23 = smd 1 x 1.4: 1 -0.95,-1.1; 2 0.95,-1.1; 3 0,1.1
RESC1608X50N = smd 0.85 x 1: 1 -0.75,0; 2 0.75,0
RESC1608X38N = smd 0.95 x 1: 1 -0.8,0; 2 0.8,0
R0603 = smd 1.1 x 1: 1 -0.85,0; 2 0.85,0
RESC1608X55N = smd 0.8 x 0.95: 1 -0.8,0; 2 0.8,0
R2010 = smd 1.8 x 2.7: 1 -2.2,0; 2 2.2,0
SJ = smd 1.168 x 1.6: 1 -0.762,0; 2 0.762,0
VIA-3.2MM-HOLE = drill 0.32 round: 1 0,0
VIA-1MM-HOLE = drill 1 round: 1 0,0
ABM3B = smd 1.8 x 1.2: 1 -2,-1.2; 2 2,-1.2; 3 2,1.2; 4 -2,1.2

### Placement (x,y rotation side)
+  29.81,6.55 270 bottom
-  41.24,6.55 270 bottom
C1  7.4,49.4 180 top
C2  7.4,46.2 0 top
C3  7.33,35.83 180 top
C4  7.4,55.4 0 top
C5  11.8,51.4 0 top
C6  12.2,47 180 top
C7  33.2,39.4 270 top
C8  23.27,117.92 90 top
C9  28.2,99.8 180 top
C10  28.07,106.22 90 top
C11  70,81 180 top
C12  82,70.5 180 top
C13  111.5,70 90 top
C14  111.2,61 270 top
C15  110,70 90 top
C16  109.7,61 270 top
C17  108.5,70 90 top
C18  117.5,70 90 top
C19  115.5,70 90 top
C20  113.2,70 90 top
C21  114.2,61 90 top
C22  104.5,70 90 top
D1  82,73 180 top
ENTER  18.38,6.55 270 bottom
F1  19,116.6 270 top
H1  176.53,5.08 0 top
H2  176.53,129.54 0 top
H3  5.08,129.54 0 top
H4  5.08,5.08 0 top
IC1  23,44.6 270 top
IC2  28.8,96 180 top
IC4  77,77 270 top
J1  26.68,22.85 270 bottom
J2  6.36,68.57 270 bottom
J3  16.52,22.85 270 bottom
J4  6.36,22.85 270 bottom
J5  16.52,68.57 270 bottom
J6  26.68,68.57 270 bottom
J7  11.68,118.38 0 bottom
J8  16.52,87.54 270 bottom
J9  36.84,68.57 270 bottom
J10  17.44,108.99 90 top
J11  23.93,104.98 90 bottom
J12  119,91 0 bottom
J13  38,128 0 top
J14  62,128 0 top
J17  50,128 0 top
L1  11.8,53.8 0 top
L2  77,82 0 top
LCD1  119,91 0 bottom
LED1  38.2,51 180 top
LED2  38.2,45.8 180 top
LED3  38.2,40.6 180 top
MENU/CANCEL  52.67,6.55 270 bottom
Q1  64,118 270 top
R1  7.4,51.4 0 top
R2  7.4,53.4 180 top
R3  35.4,36.2 270 top
R4  18.38,6.55 180 top
R5  41.24,6.55 180 top
R6  29.81,6.55 180 top
R7  40.2,36.2 270 top
R8  37.8,36.2 270 top
R9  52.67,6.55 180 top
R10  23.82,94.81 90 top
R11  70,79 0 top
R12  58,42 270 top
R13  64,42 270 top
R14  70,77 0 top
R15  84,79 0 top
R16  60,118 90 top
R17  62,123 180 top
R18  70,75.1 180 top
R23  29.84,122.56 90 top
SJ1  13.34,130.18 90 top
SJ2  55,42 270 top
SJ3  61,42 270 top
SJ4  51,45 180 top
SJ5  51,48 180 top
SJ6  6.4,31.9 90 top
SW5  7.09,87.54 0 bottom
TP1  24.66,35.06 0 top
TP2  17.18,33.62 0 top
TP3  17.14,34.92 0 top
TP4  30.43,52.36 0 top
TP5  14.2,51.5 0 top
TP6  14,49.1 0 top
TP8  33.5,118 0 top
TP9  10.6,56.84 0 top
TP10  12.16,89.99 0 top
TP11  26.04,113.67 0 top
TP12  26.04,116.2 0 top
TP13  75,86 180 top
TP14  78,86 180 top
TP15  52.7,108.3 0 top
TP16  24.13,126.36 0 top
TP17  24.13,128.91 0 top
TP18  167.64,7.62 0 top
TP19  167.64,5.08 0 top
TP20  85,77 180 top
TP21  80.5,82 180 top
TP22  83,82 180 top
Y1  7.49,41.27 270 top

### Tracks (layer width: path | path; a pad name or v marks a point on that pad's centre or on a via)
!LCD_CS1  (via drill 0.2, 0.3, 0.32)
  Top 0.152: IC1.39 21.8,35.8 20.6,34.6 20.6,26.53 19.8,25.73 19.8,24.53 18.2,22.93 17.85,22.93 J3.5 17.79,22.89 17.8,22.9 17.2,22.9 16,24.1 14.4,24.1 13.9,24.6 v13,24.6 | v127.95,31.9 128,32 128,66.7 128.6,67.3 v128.6,67.7 128.6,70.6 121.8,77.4 121.8,92.5 122.4,93.1 v122.45,93.14
  Bottom 0.152: v13,24.6 13,28.6 14,29.6 21.2,29.6 23.5,31.9 v127.95,31.9 | v122.45,93.14 122.4,93.1 122.25,92.95 LCD1.3 | v128.6,67.7 J12.41
!LCD_CS2
  Top 0.152: J3.4 15.5,25.4 16.77,24.13 18.6,24.13 19.4,24.93 19.4,26.13 20.2,26.93 20.2,35 21,35.8 IC1.38
!LCD_CS3
  Top 0.152: J3.2 16.45,26.73 18.6,26.73 19.4,27.53 IC1.36
!LCD_RST  (via drill 0.2, 0.3)
  Top 0.152: IC1.37 20.2,35.8 19.8,35.4 19.8,27.33 18.43,25.96 18.34,25.96 J3.3 | v127.35,31.3 127.4,31.5 v127.4,68.3 127.4,71.1 121.25,77.25 v121.25,92.93
  Bottom 0.152: J3.3 23.7,31.3 v127.35,31.3 | v121.25,92.93 LCD1.5 | v127.4,68.3 J12.39
!RESET  (via drill 0.32)
  Top 0.152: R1.1 6.6,51.4 C1.2 v6.6,48.4 | IC1.20 16.4,48.2 v16.6,48.4 | J8.5 17.79,84.97 17.78,84.96 16.51,86.23 14.61,86.23 12.2,88.64 12.2,89.91 12.16,89.95 TP10.1
  Bottom 0.152: v16.6,48.4 16.4,48.4 16,48 12.53,48 11.53,49 10.2,49 10,49 7.2,49 v6.6,48.4 6.11,48.4 5,49.51 5,49.5 3.23,51.27 3.23,61.34 | 3.23,61.34 3.23,83.4 4.12,84.29 SW5.B' 4.84,90.76 4.81,90.79 | 4.81,90.79 4.8,90.8 | 4.81,90.79 SW5.B 4.89,90.79 6.1,92 10.23,92 12.19,90.04 12.16,90.01 TP10.1 | J9.6 36.83,67.31 36.83,62.61 35.56,61.34 3.23,61.34
!SS
  Top 0.152: IC1.10 21.8,53 11.8,63 11.8,67.07 11,67.87 11,68.67 10.2,69.47 10.2,70.67 9.4,71.47 9.4,72.27 8.02,73.65 J2.1 7.63,73.67 7.75,73.79 7.75,78.74 10.92,81.92 10.92,91.06 15.47,95.61 R10.2 23.82,95.58 23.8,95.56 | J10.2 8.8,103.2 10.6,105 20.6,105 21.8,103.8 21.8,100.2 23.4,98.6 23.8,98.6 | 23.8,98.6 23.83,98.63 J11.1 | 23.8,95.56 23.8,98.6 | 23.8,95.56 23.75,95.5
+3V3  (via drill 0.32)
  Top 0.152: 23.89,103.71 J11.3 | 15.27,17.77 16.4,18.85 18.6,18.85 19.63,17.77 25.39,17.77 J1.10 | 8.2,51.4 R1.2 | 8.15,53.35 R2.1 8.4,53.6 | L1.1 10.8,53.8 10.6,53.6 | 13,47.4 C6.1 | 6.2,47.4 4.6,45.8 4.6,30.2 3.8,29.4 3.8,19.06 J4.10 5.09,17.79 5.1,17.8 6.3,16.6 8.7,16.6 9.87,17.77 15.23,17.77 J3.10 | 30.6,41 IC1.52
  Top 0.203: 23.83,103.77 23.8,103.8 | J3.10 15.27,17.77 | 6.2,47.4
  Top 0.254: 8.2,51.4 C1.1 8.25,49.4 | 8.4,53.6 10.6,53.6 | 13,48 11,48 v10.8,48.2 | 13,48 13.6,48 14.2,47.4 IC1.21 v17.4,47.4 | 13,48 13,47.4 | 8.6,48.2 8.2,48.6 8.2,49.35 8.25,49.4 | C7.1 32.4,40.2 31.6,41 30.6,41 28.6,41 27.8,41.8 v27.8,47.4 | R10.1 23.82,92.89 23.75,92.84 | 15.28,90.08 J8.2 | 8.25,49.4 8.26,49.4 | R2.1 8.19,53.4 8.13,53.34 8.15,53.32 R1.2
  Top 0.305: J10.4 8.6,105.4 9.8,106.6 21.4,106.6 23.8,104.2 23.8,103.8 23.89,103.71 | C10.1 28.18,103.77 28.19,103.76 | 30.73,94.64 30.69,94.7 | 25.65,92.84 25.68,92.86
  Top 0.406: v10.8,48.2 8.6,48.2 7.8,47.4 6.2,47.4 6,47.4 4.8,48.6 4.8,63.22 J2.10 | 25.68,103.77 23.83,103.77 | 25.68,103.77 C10.1 | 30.69,94.7 IC2.5 | 30.73,92.84 30.73,75.95 J9.4 | 30.73,92.84 30.73,94.64 | 30.73,92.84 25.65,92.84 23.75,92.84 18.03,92.84 15.28,90.08 | 25.68,92.86 25.68,103.77
  Bottom 0.254: v17.4,47.4 v27.8,47.4 | 23.88,103.76 J11.3
  Bottom 0.305: 33.6,118 TP8.1 31.8,118
  Bottom 0.406: J2.10 6.35,62.23 15.24,62.23 | 15.24,62.23 25.4,62.23 | 25.4,62.23 32.51,62.23 33.78,63.5 33.78,70.48 34.41,71.11 J9.4 | 15.24,62.23 15.24,62.36 15.25,62.37 J5.10 | 25.4,62.23 25.4,62.36 25.41,62.37 J6.10 | J9.4 | J9.4 | 23.88,103.76 26.04,105.92 TP11.1 27.46,113.67 31.8,118 31.8,123 35.5,126.7 | 35.5,126.7 J13.1 J13.2 35.46,129.36 36.9,130.8 46,130.8 47.5,129.3 J17.2 47.46,126.76 | 47.43,126.73 47.4,126.7 | 47.43,126.73 J17.1 | 47.46,126.76 47.43,126.73 | J17.1 47.5,126.7 47.53,126.73 J17.3 | 35.5,126.7 J13.1 | 35.5,126.7 35.53,126.73 J13.3 38,126.7 | 47.46,126.76 47.5,126.8 | 47.46,126.76 J17.1
+5V  (via drill 0.32, 0.8)
  Top 0.152: TP12.1 25.4,115.57 23.5,115.57
  Top 0.254: R3.2 34.12,35.35 v33.02,36.45
  Top 0.305: 23.26,115.34 23.2,115.4 C8.1 | C8.1 | 23.5,115.57 23.39,115.47 C8.1 | 28.96,99.69 29,99.74 C9.1 29.06,99.8
  Top 0.406: v3,90.2 4.6,88.6 4.6,86.6 3.4,85.4 3.4,36.86 v3.43,36.83 | IC2.1 29.75,98.14 29.46,98.42 28.96,98.42 | 28.96,99.69 28.96,98.42 | IC2.3 27.85,98.21 28.07,98.42 28.96,98.42 | 23.24,115.44 C8.1 23.27,115.43 23.3,115.4 | 18.92,112.6 18.92,112.65 19,112.73
  Top 0.61: v6.6,112.6 18.92,112.6 22.18,112.6 23.24,113.67 | 23.24,115.44 23.24,113.67 | 19,112.73 F1.2 | 29.06,99.8 30.35,101.09 30.35,110.24 28.57,112.01 25.65,112.01 24,113.67 23.24,113.67 | 23.3,115.4 23.3,117.1 24.2,118 28.4,118 v32.1,114.3 | 139,54 LCD1.T1_A | 139,54 LCD1.U1_A | v140.1,114.2 140.1,57.8 139.1,56.8 139.1,54.2 139,54.1 139,54
  Bottom 0.254: 3.43,36.7 32.77,36.7 v33.02,36.45
  Bottom 0.406: v6.6,112.6 3.6,112.6 3,112 v3,90.2 | v3.43,36.83 3.43,36.7
  Bottom 0.61: v32.1,114.3 140,114.3 v140.1,114.2
AVCC  (via drill 0.32)
  Top 0.152: v17,50.6 16.2,51.4 16.2,52.2 v15.8,52.6 | C5.1 11,52.2 11.4,52.6 12.2,52.6 12.6,53 12.6,53.8 L1.2 12.8,53.8 | 12.8,53.8 v14.2,53.8 | TP9.1 10.96,56.84 12.8,55 12.8,53.8 | v28,50.6 IC1.64
  Bottom 0.152: v14.2,53.8 15.2,53.8 15.8,53.2 15.8,53.18 v15.8,52.6 | v17,50.6 v28,50.6
EL1
  Top 0.254: TP22.1 84.8,80.2 R15.2
  Bottom 0.254: TP22.1 83.81,81.19 LCD1.U1_EL1 126.71,81.19 140.1,67.8 141.4,67.8 LCD1.T1_EL1
EL2
  Top 0.254: IC4.7 81.97,77.64 82.6,77 TP20.1
  Bottom 0.254: TP20.1 85,75.4 85.71,74.69 LCD1.U1_EL2 129.31,74.69 | 129.31,74.69 129.3,74.7 | 129.31,74.69 135.4,68.6 135.4,64.5 137,62.9 LCD1.T1_EL2
FOO  (via drill 0.32)
  Top 0.152: v12.6,50.2 C5.2 | C2.2 | 17.4,109 17.41,108.99 J10.GND1 | 8.26,46.2 8.25,46.2 C2.2 | IC1.22 | IC1.63 | IC1.53
  Top 0.203: v33.2,37.6 C7.2 | LED1.K LED2.K LED3.K 35.8,41.4 35.4,41.8 | 30.6,41.8 | IC1.53 30.6,41.8 | J10.GND3 3.29,97.91
  Top 0.254: 28.13,108.67 28.2,108.6 | C10.2 28.13,108.67 | 28.13,108.67 28.01,108.79 | 17.4,109 17.41,108.99 J10.GND1
  Top 0.406: Y1.4 8.69,43.36 9.67,44.34 v10.06,44.34 | Y1.2 6.29,39.17 6.4,39.06 v6.4,37.51 | C12.2 81.1,70.5 | IC4.4 72.2,75.09 72.2,75.1 70.9,75.1
  Bottom 0.305: v122.81,92.3 122.7,92.3 122.75,92.25 LCD1.2 122.75,90.15 122.75,90.14 | v105.81,67.3 v105.8,67.3 J12.3 | v117.91,67.2 117.81,67.19 117.8,67.2 J12.23
  other vias: 23.81,45.4 7.62,58.1 6.5,34.48 22.23,45.4 4.6,76.6 9.53,46.83 22.23,43.81 23.81,43.81 33.97,42.55
  pour Bottom (rank 2, hatched): 1.91,132.72 179.71,132.72 179.71,1.91 1.91,1.91
  pour Top (rank 2, hatched): 1.71,132.72 179.71,132.72 179.71,1.91 1.91,1.91
GND1
  pour Bottom (rank 2): 101.35,5.84 101.35,10.92 97.54,13.97 93.47,13.97 91.44,12.45 67.31,12.45 67.31,4.06 91.44,4.06 93.47,2.54 97.54,2.54
GND2
  pour Bottom: 162.36,130.18 arc-90 163,130.81 166.79,130.81 arc-90 167.43,130.18 167.43,127.64 arc-90 166.79,127 163,127 arc-90 162.36,127.64
GNDA
  Top 0.203: 0.64,87.63 0.68,87.58 0.72,87.54 | 29.97,0.64 29.97,0.51 29.81,0.67 | 41.15,0.64 41.15,0.76 41.19,0.81 41.24,0.85
  Top 0.254: 13.4,134 13.4,133.99 13.4,131 SJ1.2 | R23.2 29.8,123.4 29.8,133.99 | 0.64,87.6 0.6,87.6 | 0.68,87.58 0.7,87.6 2.93,87.6 SW5.G | ENTER.G 18.4,2.43 18.4,0.64 | 29.81,0.67 29.8,0.68 +.G | 41.19,0.81 41.2,0.8 41.2,2.41 -.G | MENU/CANCEL.G 52.7,2.42 52.7,0.64 | H1.B3,2 | 134.4,133.99 134.4,133.9 134.35,133.85 | 140.6,0.64 140.6,0.8 140.55,0.85
  Top 0.406: SJ1.2 12.7,130.81
  Top 1.016: 5.06,129.54 H3.B3,2 0.62,134 | 0.64,0.7 0.7,0.7 H4.B3,2 | H1.B3,2 180.9,0.7 | 180.97,133.99 180.99,134 | 180.99,134 H2.B3,2 | 180.99,134 181,134 | 0.64,133.99 0.62,134 | 0.62,134 0.6,134
  Top 1.422: 0.64,133.99 13.4,133.99 29.8,133.99 134.4,133.99 180.97,133.99 180.97,0.64 140.6,0.64 52.7,0.64 41.15,0.64 29.97,0.64 18.4,0.64 0.64,0.64 0.64,0.7 0.64,87.6 0.64,87.63 0.64,133.99
  Bottom 1.016: H3.B3,2 5.06,129.54 | 0.64,0.8 0.8,0.8 H4.B3,2 | 180.97,0.62 181,0.6 | 180.97,0.64 180.97,0.62 | H1.B3,2 180.97,0.62
  Bottom 1.422: 0.64,133.99 180.97,133.99 180.97,0.64 0.64,0.64 0.64,0.8 0.64,133.99
LCD_D0  (via drill 0.2, 0.3)
  Top 0.152: IC1.51 | IC1.51 | IC1.51 31.4,40.2 32.2,39.4 32.2,37.8 31.4,37 31.4,35 28,31.6 28,27.98 J1.1 | v125,68.3 125,28.6 v125.05,28.51 v125.04,28.5 | v125,68.3 125,70.7 119.25,76.45 v119.25,92.93 | v125,68.3 125,68.2
  Bottom 0.152: J1.1 27.97,27.93 28,27.9 28.9,27.9 29.5,28.5 v125.04,28.5 | v119.25,92.93 LCD1.9 | v125,68.3 J12.35
LCD_D1  (via drill 0.2, 0.3)
  Top 0.152: IC1.50 | IC1.50 | IC1.50 31.4,39.4 31.8,39 31.8,38.2 30.6,37 30.6,35 25.4,29.8 J1.2 | v124.45,27.8 124.4,27.9 v124.4,67.7 124.4,70.6 118.75,76.25 v118.75,92.3
  Bottom 0.152: J1.2 25.41,27.91 25.4,27.9 26.65,26.65 29.05,26.65 30.2,27.8 v124.45,27.8 | v118.75,92.3 LCD1.10 | v124.4,67.7 J12.34
LCD_D2  (via drill 0.2, 0.3)
  Top 0.152: IC1.49 30.7,38.1 29.8,37.2 29.8,35 24.2,29.4 24.2,27.2 24.8,26.6 26.6,26.6 27.81,25.39 J1.3 | v123.85,27.1 123.8,27.2 v123.8,68.3 123.8,70.5 118.25,76.05 v118.25,92.93
  Bottom 0.152: J1.3 27.95,25.35 28,25.3 28.9,25.3 30.7,27.1 v123.85,27.1 | v118.25,92.93 LCD1.11 | v123.8,68.3 J12.33
LCD_D3  (via drill 0.2, 0.3)
  Top 0.152: 29,35 IC1.48 | 29,35 29,35.8 | 29,35 23.8,29.8 23.8,26.8 25.21,25.39 J1.4 | v123.25,26.4 123.2,26.5 v123.2,67.7 123.2,70.4 117.75,75.85 v117.75,92.3
  Bottom 0.152: J1.4 26.7,24.1 28.8,24.1 31.1,26.4 v123.25,26.4 | v117.75,92.3 LCD1.12 | v123.2,67.7 J12.32
LCD_D4  (via drill 0.2, 0.3)
  Top 0.152: 28.2,35 IC1.47 | 28.2,35 23.4,30.2 23.4,26.2 24.2,25.4 24.2,24.4 24.6,24 26.6,24 27.75,22.85 27.93,22.85 J1.5 | 28.2,35 28.2,35.4 | v122.65,25.6 122.6,25.7 v122.6,68.3 122.6,70.3 117.25,75.65 v117.25,92.93
  Bottom 0.152: J1.5 28,22.8 28.9,22.8 31.7,25.6 v122.65,25.6 | v117.25,92.93 LCD1.13 | v122.6,68.3 J12.31
LCD_D5  (via drill 0.2, 0.3)
  Top 0.152: 27.4,35 IC1.46 | 27.4,35 27.4,35.8 | 27.4,35 23,30.6 23,25.8 23.8,25 23.8,23.8 24.75,22.85 25.39,22.85 J1.6 | v122.05,24.8 122,24.8 v122,67.7 122,70.2 116.75,75.45 v116.75,92.3
  Bottom 0.152: 25.41,22.89 25.4,22.9 | J1.6 25.41,22.89 | 25.41,22.89 26.7,21.6 28.9,21.6 32.1,24.8 v122.05,24.8 | v116.75,92.3 LCD1.14 | v122,67.7 J12.30
LCD_D6  (via drill 0.2, 0.3, 0.32)
  Top 0.152: 26.6,35 IC1.45 | 26.6,35 26.6,35.8 | 26.6,35 22.6,31 22.6,25.4 23.4,24.6 23.4,23.4 23.8,23 23.8,22.2 24.4,21.6 26.6,21.6 27.89,20.31 J1.7 | SJ4.1 51.76,24.26 v51.7,24 | v121.45,24 121.4,24 v121.4,68.3 121.4,70.1 116.25,75.25 v116.25,92.92
  Bottom 0.152: J1.7 27.99,20.31 28,20.3 28.9,20.3 32.6,24 v51.7,24 v121.45,24 | v116.25,92.92 LCD1.15 | v121.4,68.3 J12.29
LCD_D7  (via drill 0.2, 0.3, 0.32)
  Top 0.152: IC1.44 25.8,35.8 25.8,35 22.2,31.4 22.2,25 23,24.2 23,23 23.4,22.6 23.4,21.4 24.49,20.31 J1.8 | SJ5.1 52.8,48 53,47.8 v53,23.2 | v120.85,23.2 120.8,23.3 v120.8,67.7 120.8,70 115.75,75.05 v115.75,92.3
  Bottom 0.152: J1.8 25.41,20.21 25.4,20.2 26.6,19 28.7,19 32.9,23.2 v53,23.2 v120.85,23.2 | v115.75,92.3 LCD1.16 | v120.8,67.7 J12.28
LCD_D/!I  (via drill 0.2, 0.3)
  Top 0.152: J3.8 15.2,20.26 15.2,20.13 16.4,19.23 18.5,19.23 19,19.73 19,20.53 19.8,21.33 19.8,22.13 21,23.33 21,24.53 21.8,25.33 21.8,33.4 24.2,35.8 IC1.42 | v126.75,30.6 126.8,30.7 v126.8,67.7 126.8,71 120.75,77.05 v120.75,92.3
  Bottom 0.152: J3.8 15.21,20.31 15.2,20.3 13.8,21.7 13.8,23.6 14.3,24.1 18.6,24.1 19.2,24.7 19.2,26 23.8,30.6 v126.75,30.6 | v120.75,92.3 LCD1.6 | v126.8,67.7 J12.38
LCD_E  (via drill 0.2, 0.3)
  Top 0.152: 15.2,22.9 15.2,22.93 | J3.6 15.2,22.9 | 15.2,22.9 15.2,22.73 16.4,21.53 18.4,21.53 19,22.13 19,22.93 20.2,24.13 20.2,25.33 21,26.13 21,34.2 22.6,35.8 IC1.40 | v125.55,29.2 125.6,29.3 v125.6,67.7 125.6,70.8 119.75,76.65 v119.75,92.3
  Bottom 0.152: J3.6 15.2,22.8 16.5,21.5 16.5,19.5 17,19 18.6,19 20.4,20.8 20.4,25.6 24,29.2 v125.55,29.2 | v119.75,92.3 LCD1.8 | v125.6,67.7 J12.36
LCD_R/!W  (via drill 0.2, 0.3)
  Top 0.152: J3.7 17.8,20.33 18,20.33 19.4,21.73 19.4,22.53 20.6,23.73 20.6,24.93 21.4,25.73 21.4,33.8 23.4,35.8 IC1.41 | v126.15,29.9 126.2,30 v126.2,68.3 126.2,70.9 120.25,76.85 v120.25,92.92
  Bottom 0.152: J3.7 19.8,22.3 19.8,25.8 23.9,29.9 v126.15,29.9 | v120.25,92.92 LCD1.7 | v126.2,68.3 J12.37
LCD_VDD  (via drill 0.3, 0.32)
  Top 0.152: SJ3.1 61,42.8 R12.1
  Top 0.305: v104.5,67.6 104.5,69.1 C22.1
  Top 0.406: J17.5 52.54,108.46 TP15.1 v52.7,93.9 52.7,57.1 58,51.8 R12.1 | 104.5,69.1 103.4,69.1 102.8,69.7 v102.8,93.9
  Bottom 0.152: LCD1.4 121.75,92.35 121.9,92.5 121.9,93.9
  Bottom 0.305: LCD1.1 123.25,91.65 123.6,92 123.6,93.7 123.4,93.9 121.9,93.9 | J12.40 128,64.2 127.8,64 120.2,64 | 107.6,64 105.5,64 105.2,64.3 J12.2 105.2,66.6 104.5,67.3 v104.5,67.6 | 107.6,64 108.2,64 | 108.2,64 109.2,63 117.4,63 118.4,64 | 118.4,64 119,64 | 119,64 119.6,64 | 119.6,64 120.2,64 | 107.6,64 J12.6 | 108.2,64 J12.7 | 120.2,64 J12.27 | 119.6,64 J12.26 | 119,64 J12.25 | 118.4,64 J12.24 | 102.6,93.9 v102.8,93.9
  Bottom 0.406: J17.4 52.47,129.27 52.5,129.3 J17.6 52.54,126.86 52.6,126.8 J17.5 | v52.7,93.9 102.6,93.9 | v102.8,93.9 121.9,93.9
LED1  (via drill 0.32)
  Top 0.152: IC1.26 14.5,43.4 12.2,41 12.2,34.2 9.4,31.4 9.4,27.93 | 9.4,27.93 9.4,27.73 | 9.4,27.93 9.4,27.53 8.6,26.73 6.29,26.73 J4.2 | R7.2 40.2,34.6 39.4,33.8 32.05,33.8 30.2,31.97 30.2,13.6 v30.4,13.4
  Bottom 0.152: v30.4,13.4 13.56,13.4 13.5,13.41 13.44,13.46 11.02,15.88 11.02,24.55 8.87,26.7 6.32,26.7 J4.2
LED2  (via drill 0.32)
  Top 0.152: IC1.27 | IC1.27 14.6,42.6 12.6,40.6 12.6,33.8 9.8,31 9.8,26.93 8.3,25.43 | 8.3,25.43 | J4.3 8.26,25.39 8.3,25.43 | v29.8,12.8 29.8,32.22 31.78,34.2 37.4,34.2 37.8,34.6 R8.2
  Bottom 0.152: J4.3 9.41,25.39 10.72,24.08 10.72,15.69 13.41,13 29.6,13 v29.8,12.8
LED_BL-  (via drill 0.8)
  Top 0.61: 102.2,54 LCD1.T1_K 99,54 | LCD1.U1_K 99,54 | 99,54 99,58.5 95.1,62.4 v95.1,126.71 v95.09,126.72
  Bottom 0.406: J14.4 64.43,129.27 64.5,129.2 64.54,129.24 J14.6 64.54,126.94 64.5,126.9 64.54,126.86 J14.5
  Bottom 0.61: J14.5 v95.09,126.72
M80/!68  (via drill 0.2, 0.3, 0.32)
  Top 0.152: R13.2 64.1,41.1 | SJ3.2 63.96,41.24 R13.2 | v64,33.5 R13.2 | v108.35,33.5 108.4,33.5 108.1,33.8 108.1,63.4 107,64.5 v107,67.7 107,71.6 115.25,79.85 v115.25,92.92
  Bottom 0.152: v115.25,92.92 LCD1.17 | v64,33.5 v108.35,33.5 | v107,67.7 J12.5
MISO
  Top 0.152: J2.4 5.36,71.11 6.6,69.87 8.2,69.87 9,69.07 9,68.27 9.8,67.47 9.8,66.67 10.6,65.87 10.6,61.8 19.4,53 IC1.13 | J10.7 13.5,108.7 15.8,111 23,111 23.33,111.33 J11.6
  Bottom 0.152: J2.4 5.2,71.11 5.21,71.12 3.94,72.39 3.94,74.3 11.05,81.41 11.05,86.11 13.84,88.9 13.84,90.55 14.73,91.44 17.27,91.44 17.79,90.92 J8.1 19.59,90.08 20.19,90.68 20.19,107.7 23.88,111.38 J11.6
MOSI  (via drill 0.32)
  Top 0.152: J2.3 8.16,71.11 9.4,69.87 9.4,68.67 10.2,67.87 10.2,67.07 11,66.27 11,62.2 20.2,53 IC1.12 20.2,50.1 v20,49.9 | J10.3 8.7,104.3 10.2,105.8 21,105.8 22.6,104.2 22.6,102.2 23.97,101.17 | 23.97,101.17 24,101.2 | J11.2 23.97,101.17 | v49,48 SJ5.2
  Bottom 0.152: J2.3 7.74,71.11 11.94,75.31 11.94,85.47 14.01,87.54 J8.4 15.46,87.54 16.64,86.36 18.29,86.36 21.21,89.28 21.21,98.42 23.95,101.17 | 23.95,101.17 24,101.22 | 23.95,101.17 J11.2 | v20,49.9 33.8,49.9 35,48.7 48.3,48.7 v49,48
N$1
  Top 0.152: IC1.23 11.89,45.8 11.09,45 6.65,45 6.6,44.96 | 6.6,44.96 6.6,43.68 6.22,43.31 | 6.6,44.96 C2.1 | 6.22,43.31 6.2,43.28 | Y1.1 6.22,43.27 6.22,43.31
N$2
  Top 0.152: 21.6,4.4 21.63,4.37 ENTER.B' | 21.6,4.4 21.5,4.3 | 21.6,4.4 21.6,6 21,6.6 19.2,6.6 19.18,6.58 R4.1
  Bottom 0.152: 21.59,4.3 ENTER.B' | ENTER.B 21.59,4.3 | 21.59,4.3 21.59,4.29
N$3
  Top 0.152: IC1.24 12.23,45 10.41,43.18 10.41,41.27 8.69,39.55 Y1.3 8.69,39.31 8.64,39.37 8.64,37.47 8.13,36.96 C3.1
N$4
  Top 0.152: 44.43,4.4 44.49,4.34 -.B' | 44.43,4.4 44.33,4.3 | 44.43,4.4 44.43,6 43.83,6.6 42.03,6.6 42.04,6.59 R5.1
  Bottom 0.152: -.B' 44.5,4.32 | -.B' | -.B -.B'
N$5
  Top 0.152: IC1.19 14.2,49 TP6.1
N$6
  Top 0.152: 33.08,4.3 +.B' 33.06,5.93 32.44,6.55 30.73,6.55 30.72,6.57 30.7,6.55 R6.1
  Bottom 0.152: +.B 26.51,4.3 26.82,3.99 32.89,3.99 +.B'
N$7
  Top 0.152: R7.1 41.58,37.05 42.45,37.93 42.45,42.75 41.8,43.4 41.8,47.8 40.6,49 LED1.A
N$8
  Top 0.152: 55.94,4.3 MENU/CANCEL.B' 55.92,5.85 55.22,6.55 53.54,6.55 53.53,6.55 R9.1
  Bottom 0.152: 55.88,4.3 MENU/CANCEL.B' | MENU/CANCEL.B 55.88,4.3 | 55.88,4.3 55.88,4.29
N$9  (via drill 0.32)
  Top 0.152: v29.39,49 IC1.62 | v5.8,50.4 5.8,53 6.2,53.4 R2.2 C4.1
  Bottom 0.152: v5.8,50.4 5.8,49.8 6.2,49.4 9.6,49.4 9.8,49.4 11.8,49.4 12.8,48.4 15.6,48.4 16.4,49.2 29.19,49.2 v29.39,49
N$10
  Top 0.152: R8.1 37.8,37.8 38.2,38.2 41.4,38.2 41.8,38.6 41.8,42.6 40.6,43.8 LED2.A
N$11
  Top 0.152: TP1.1 25,35.4 IC1.43
N$12
  Top 0.406: C12.1 82.95,70.55 82.9,70.6 83.7,71.4 D1.C
  Top 0.61: IC4.6 81.23,76.36 83.3,74.3 83.3,73.3 83.6,73 D1.C
N$13
  Top 0.152: IC1.34 17.8,35.74 18.02,35.42 18.02,34.26 TP2.1
N$14
  Top 0.61: J7.1 14.68,119.48 15.4,120.2 18.2,120.2 19,119.4 F1.1 19,118.2
N$15
  Top 0.152: IC1.33 17,35.07 TP3.1
N$16
  Top 0.152: 83.11,78.91 83.19,78.91 83.2,78.9 R15.1
  Top 0.254: IC4.8 82,78.91 | 82,78.91 83.11,78.91 | TP21.1 80.5,81.8 82,80.3 82,78.91 | 82,78.91 82,79.2
N$17
  Top 0.152: R3.1 35.4,37.8 36.2,38.6 40.2,38.6 40.6,39 LED3.A
N$18
  Top 0.152: IC1.18 14.55,49.8 14.2,50.2 TP5.1
N$19
  Top 0.152: 30.4,52.36 30.4,52.4 | 30.4,52.36 TP4.1 | IC1.1 30.4,52.3 30.4,52.36
N$20
  Top 0.152: IC4.2 72.67,77.64 71.3,79 R11.2
N$21
  Top 0.152: IC4.3 72.23,76.36 71.6,77 R14.2
N$22  (via drill 0.8)
  Top 0.406: C11.1 v70.85,123
  Top 0.508: 75.8,81.9 75.85,81.95 L2.1
  Top 0.61: 75.8,81.9 75.8,79.5 75.2,78.91 IC4.1 73,78.91 72.5,79.4 72.5,80.7 72.2,81 C11.1
  Bottom 0.406: J13.4 40.47,129.27 40.5,129.3 J13.6 J13.5 | v70.85,123 41.93,123 40.54,124.39 40.54,126.66 40.5,126.7 J13.5 | J13.5
N$25
  Top 0.406: J14.1 59.46,126.76 59.5,126.8 59.8,126.5 R17.2
  Bottom 0.406: J14.1 59.5,126.7 | J14.1 61.87,126.73 61.9,126.7 61.93,126.73 J14.3 | J14.2 J14.1
N$28  (via drill 0.3)
  Top 0.254: v117,67.6 117.5,68.1 117.5,69.1 C18.1
  Bottom 0.254: J12.22 117.2,67.4 v117,67.6
N$29  (via drill 0.3)
  Top 0.254: v114.4,67.9 114.4,70.8 | C19.2 115.45,70.85 115.4,70.8 114.4,70.8 | C20.2 113.2,70.8 114.4,70.8
  Bottom 0.254: J12.19 115.4,66.9 v114.4,67.9
N$30
  Top 0.406: R17.1 64.2,121.2 65.1,120.3 Q1.3
N$31
  Top 0.152: R16.2 60.1,118.8 60.2,118.7 60.45,118.95 Q1.1
N$32
  Top 0.61: 78.15,75.14 78.2,75.1 80,75.1 80,75.09 IC4.5 | 78.15,75.14 L2.2 | D1.A 78.6,73 78.15,73.45 78.15,75.14
N$33  (via drill 0.3)
  Top 0.254: C19.1 115.5,69 v115.5,67.8
  Bottom 0.254: J12.20 116,67.3 v115.5,67.8
N$34  (via drill 0.3)
  Top 0.254: C20.1 113.2,69.2 v113.2,67.3
  Bottom 0.254: J12.18 114.8,66.7 114.4,67.1 113.4,67.1 v113.2,67.3
N$35  (via drill 0.3)
  Top 0.152: C21.2 114.25,61.85 114.3,61.9 114.2,62
  Top 0.254: 114.2,62 v114.2,63.7
  Bottom 0.254: v114.2,63.7 J12.17
N$36  (via drill 0.3)
  Top 0.152: C21.1 114.2,60.1 114.1,60.2
  Top 0.254: v113.3,63.7 113,63.4 113,60.5 113.3,60.2 114.1,60.2
  Bottom 0.254: J12.16 113.6,64 v113.3,63.7
N$37  (via drill 0.3)
  Top 0.254: C13.1 v111.5,67.7
  Bottom 0.254: J12.13 111.8,67.4 v111.5,67.7
N$38  (via drill 0.3)
  Top 0.152: C14.1
  Top 0.254: C14.1 v111.2,63.7
  Bottom 0.254: v111.2,63.7 J12.12
N$39  (via drill 0.3)
  Top 0.254: C15.1 v110,67.7
  Bottom 0.254: J12.11 110.6,67.1 v110,67.7
N$40  (via drill 0.3)
  Top 0.152: C16.1
  Top 0.254: C16.1 v109.7,63.7
  Bottom 0.254: J12.10 110,64 v109.7,63.7
N$41  (via drill 0.3)
  Top 0.254: v108.5,67.8 C17.1
  Bottom 0.254: J12.9 109.4,66.9 v108.5,67.8
PAR/!SER  (via drill 0.2, 0.3, 0.32)
  Top 0.152: R12.2 58.1,41.1 | SJ2.2 57.96,41.24 R12.2 | R12.2 57.9,41.2 58,41.1 | v58,32.7 R12.2 | 107.7,32.66 v107.7,32.7 107.5,32.9 107.5,63.3 106.4,64.4 v106.4,68.3 | v106.4,68.3 106.4,71.7 114.75,80.05 v114.75,92.3 | v106.4,68.3 106.4,67.8
  Bottom 0.152: v114.75,92.3 LCD1.18 | v58,32.7 v107.7,32.7 | v106.4,68.3 J12.4
PB6
  Top 0.152: J2.7 8.04,66.03 9.4,64.67 9.4,60.6 17,53 IC1.16
PB7
  Top 0.152: IC1.17 | J2.8 5.09,65.91 6.13,64.87 8.4,64.87 9,64.27 9,60.2 15,54.2 15,50.79 15.19,50.6 IC1.17
PC0
  Top 0.152: J3.1 19,29.21 19,35.4 18.6,35.8 IC1.35
PD0
  Top 0.152: IC1.25 | IC1.25 14.6,44.2 11.8,41.4 11.8,34.6 9,31.8 9,31.14 | J4.1 8.4,27.93 9,28.53 9,31.14 | 9,31.14 8.97,31.14 SJ6.1
PD3
  Top 0.152: IC1.28 14.7,41.8 13,40.1 13,33.4 10.2,30.6 10.2,26.6 8.8,25.2 8.8,24.9 8,24.1 6.4,24.1 J4.4
PE0
  Top 0.152: J5.1 18.02,73.65 19.4,72.27 19.4,71.47 20.2,70.67 20.2,69.47 21.4,68.27 21.4,59.8 28.2,53 IC1.2
PE1
  Top 0.152: J5.2 15.42,73.65 16.6,72.47 18.4,72.47 19,71.87 19,71.07 19.8,70.27 19.8,69.07 21,67.87 21,59.4 27.4,53 IC1.3
PE2
  Top 0.152: J5.3 18.16,71.11 19.4,69.87 19.4,68.67 20.6,67.47 20.6,59 26.6,53 IC1.4
PE3
  Top 0.152: J5.4 15.36,71.11 16.6,69.87 18.2,69.87 19,69.07 19,68.27 20.2,67.07 20.2,58.6 25.8,53 IC1.5
PE4
  Top 0.152: J5.5 17.9,68.57 19.8,66.67 19.8,58.2 25,53 IC1.6
PE5
  Top 0.152: J5.6 15.3,68.57 16.6,67.27 18.4,67.27 19.4,66.27 19.4,57.8 24.2,53 IC1.7
PE6
  Top 0.152: IC1.8 23.4,53 19,57.4 19,64.8 17.79,66.01 J5.7
PE7
  Top 0.152: IC1.9 22.6,53 16.3,59.3 16.3,65.1 15.4,66 15.28,66 J5.8
PWM1  (via drill 0.32)
  Top 0.152: 17.8,52.2 IC1.15 17.8,53 9.8,61 9.8,65.07 9,65.87 9,66.67 8.4,67.27 6.33,67.27 5.09,68.51 J2.6 | v60,91.4 R16.1
  Bottom 0.152: v60,91.4 59.6,91.8 30.7,91.8 9.8,70.9 9.8,68.8 8.3,67.3 6.3,67.3 5.09,68.51 J2.6
PWM2  (via drill 0.32)
  Top 0.152: J2.5 7.9,68.57 9.4,67.07 9.4,66.27 10.2,65.47 10.2,61.4 18.6,53 IC1.14 | v67.2,92.3 67.2,78 68.2,77 R14.1 | R11.1 69.1,79 69.2,78.9 R14.1 | 69.2,75 R18.2 R14.1
  Bottom 0.152: J2.5 7.67,68.57 9.3,70.2 9.3,71.1 30.5,92.3 v67.2,92.3
SCK  (via drill 0.32)
  Top 0.152: J2.2 5.22,73.65 6.6,72.27 8.6,72.27 9,71.87 9,71.07 9.8,70.27 9.8,69.07 10.6,68.27 10.6,67.47 11.4,66.67 11.4,62.6 21,53 IC1.11 21,48.6 v21.2,48.4 | J10.5 8.5,106.5 9.4,107.4 22.6,107.4 23.75,106.25 J11.4 | 50.3,45 SJ4.2 v49,45
  Bottom 0.152: J2.2 5.09,73.78 5.08,74.8 11.43,81.15 11.43,85.72 14.48,88.77 16.51,88.77 17.74,87.54 J8.3 17.82,87.54 20.7,90.42 20.7,103.12 23.88,106.3 J11.4 | v21.2,48.4 28.6,48.4 28.9,48.1 45.9,48.1 v49,45
SW1  (via drill 0.32)
  Top 0.152: IC1.29 | IC1.29 14.6,41 13.4,39.8 13.4,33 10.6,30.2 10.6,26.13 9.4,24.93 9.4,24.53 7.8,22.93 7.6,22.93 7.6,22.88 J4.5 | R9.2 50.95,6.55 50.6,6.2 v50.6,5.4
  Bottom 0.152: J4.5 7.62,22.86 | J4.5 | J4.5 7.65,22.84 7.84,22.71 9.8,20.75 9.8,15.47 13,12.27 13,9 15,7 17.15,7 17.93,6.22 28.71,6.22 38.73,6.22 39.5,6.22 40.32,5.4 v50.6,5.4
SW2  (via drill 0.32)
  Top 0.152: IC1.30 | IC1.30 14.6,40.2 13.8,39.4 13.8,32.6 11,29.8 11,25.73 9.8,24.53 9.8,24.13 9,23.33 9,22.13 8.4,21.53 6.2,21.53 5,22.73 5,22.76 J4.6 | v28.37,5.33 28.6,5.33 29,5.73 29,6.4 29.01,6.41 R6.2
  Bottom 0.152: J4.6 5.08,22.86 | J4.6 | J4.6 6.4,21.54 8.26,21.54 9.4,20.4 9.4,15.24 12.6,12.04 12.6,8.73 14.73,6.6 16.89,6.6 17.7,5.8 27.93,5.8 28.4,5.33 v28.37,5.33
SW3  (via drill 0.32)
  Top 0.152: IC1.31 | IC1.31 14.6,39.4 14.2,39 14.2,32.2 11.4,29.4 11.4,25.33 10.2,24.13 10.2,23.73 9.4,22.93 9.4,21.73 8,20.33 7.61,20.33 | 7.61,20.33 7.6,20.33 | J4.7 7.61,20.33 | R5.2 39.58,6.55 39.23,6.2 v39.23,5.4
  Bottom 0.152: J4.7 9,18.94 9,15 12.2,11.8 12.2,8.45 14.45,6.2 16.6,6.2 17.4,5.4 27.2,5.4 28.07,4.53 28.73,4.53 29.99,5.78 38.92,5.78 39.24,5.46 v39.23,5.4
SW4  (via drill 0.32)
  Top 0.152: IC1.32 15.3,38.1 14.6,37.3 14.6,31.8 | J4.8 5.07,20.33 5,20.33 6.2,19.13 8.2,19.13 9,19.93 9,20.53 9.8,21.33 9.8,22.53 10.6,23.33 10.6,23.73 11.8,24.93 11.8,29 14.6,31.8 | 14.6,31.8 | R4.2 17.53,6.6 16.6,6.6 16.2,6.2 v16.2,5.4
  Bottom 0.152: v16.2,5.4 15.8,5.8 14.18,5.8 11.8,8.18 11.8,11.04 11.81,11.05 11.81,11.56 8.6,14.77 8.6,15.8 7.8,16.6 7.21,16.6 6.45,17.36 6.46,18.87 5.01,20.31 | 5.01,20.31 4.99,20.33 | 5.01,20.31 J4.8
TCK
  Top 0.152: IC1.57 31.4,45 33.4,47 33.4,53.8 31.8,55.4 29.8,55.4 23.4,61.8 23.4,67.8 23.8,68.2 23.8,69 24.6,69.8 26.6,69.8 27.83,68.57 J6.5 28.83,67.69 33.02,67.69 33.9,68.57 33.91,68.57 33.91,68.58 35.13,69.8 36.15,69.8 36.83,70.48 36.83,72.52 37.97,73.66 37.98,73.65 J9.1
TDI
  Top 0.152: IC1.54 31.4,42.6 34.6,45.8 34.6,55 33,56.6 31,56.6 26.8,60.8 26.8,62.23 | J6.8 25.77,66.03 26.8,65 26.8,62.23 | J9.9 38.11,63.38 36.96,62.23 26.8,62.23 | 26.8,62.23
TDO
  Top 0.152: IC1.55 31.4,43.4 34.2,46.2 34.2,54.6 32.6,56.2 30.6,56.2 24.2,62.6 24.2,67 24.6,67.4 26.6,67.4 27.95,66.05 J6.7 27.81,65.91 28.83,66.93 32.77,66.93 34.92,64.77 38.61,64.77 39.37,65.53 39.37,69.85 J9.3
TMS
  Top 0.152: IC1.56 31.4,44.2 33.8,46.6 33.8,54.2 32.2,55.8 30.2,55.8 23.8,62.2 23.8,67.4 24.2,67.8 24.2,68.2 24.4,68.4 25.2,68.4 25.4,68.6 25.41,68.59 J6.6 26.13,68.57 27.4,67.3 36.82,67.3 J9.5 38.11,68.59
TS_X+
  Top 0.152: IC1.60 31.4,47.4 32.2,48.2 32.2,52.6 30.6,54.2 28.6,54.2 22.2,60.6 22.2,69 22.6,69.4 22.6,70.2 23.4,71 23.4,71.8 24.2,72.6 24.2,73 24.8,73.6 25.4,73.6 25.41,73.61 J6.2
  Bottom 0.152: LCD1.X+ 145.4,83 142.4,86 84.9,86 82.9,88 37.3,88 25.4,76.1 25.4,73.6 25.41,73.61 J6.2
TS_X-  (via drill 0.32)
  Top 0.152: 23.8,73.6 23.8,73 23,72.2 23,71.4 22.2,70.6 22.2,69.8 21.8,69.4 21.8,60.2 28.2,53.8 30.2,53.8 31.8,52.2 31.8,48.6 31.4,48.2 IC1.61 23.1,48.2 20.5,45.6 v20.5,43 | 23.8,73.6 23.8,74.2 24.6,75 26.6,75 J6.1 | 23.8,73.6 v23.3,73.6 | v12.2,43 11.4,42.2 11.4,34.9 9.1,32.6 6.3,32.6 6.36,32.66 SJ6.2
  Bottom 0.152: LCD1.X- 144.6,85 142.6,87 85.1,87 83.1,89 36.9,89 23.4,75.5 23.4,73.8 v23.3,73.6 | v12.2,43 v20.5,43
TS_Y+
  Top 0.152: IC1.58 31.4,45.8 33,47.4 33,53.4 31.4,55 29.4,55 23,61.4 23,68.2 23.4,68.6 23.4,69.4 24.2,70.2 24.2,70.6 24.6,71 25.4,71 25.41,71.01 J6.4
  Bottom 0.152: LCD1.Y+ 145,84 142.5,86.5 85,86.5 83,88.5 37.1,88.5 24.2,75.6 24.2,72.3 J6.4
TS_Y-
  Top 0.152: IC1.59 31.4,46.6 32.6,47.8 32.6,53 31,54.6 29,54.6 22.6,61 22.6,68.6 23,69 23,69.8 23.8,70.6 23.8,71.4 24.8,72.4 26.6,72.4 27.89,71.11 J6.3
  Bottom 0.152: LCD1.Y- 144.3,86 142.8,87.5 85.2,87.5 83.2,89.5 36.7,89.5 22.7,75.5 22.7,72.1 25,69.8 26.6,69.8 27.91,71.11 J6.3
(copper drawn outside any net)
  shapes: Top circle x3

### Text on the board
tPlace: GND | GND | WARNING | HIGH VOLTAGE | GND | GND
bPlace: 5VDC | GND | l | a | e | R | GND | I | I | I | EL_BL | VDD | LED_BL | REMOVE 3-4 SHUNT | TO MEASURE CURRENT | RoHS | microSD | Boot Loader | RESET | TOUCHSCREEN | GND | GND | ISP | WARNING | HIGH VOLTAGE | WARNING | HIGH VOLTAGE | PORTB | PORTE | PORTF | JTAG | LED1 | LED2 | POWER | PORTD | PORTC | PORTA | DO NOT HOT PLUG OR UNPLUG LCD MODULES | CFA-10021 V1.1 | GND | SW4 | SW3 | SW2 | SW1 | http://www.crystalfontz.com | GND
